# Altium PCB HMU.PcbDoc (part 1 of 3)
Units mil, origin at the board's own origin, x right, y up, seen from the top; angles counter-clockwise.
Board outline 6247.81 x 4035.43 mil, 4 copper layers (Top Layer, Mid-Layer 1, Mid-Layer 2, Bottom Layer), stack 90 mil thick; 310 components, 201 nets, 779 pads, 176 vias.
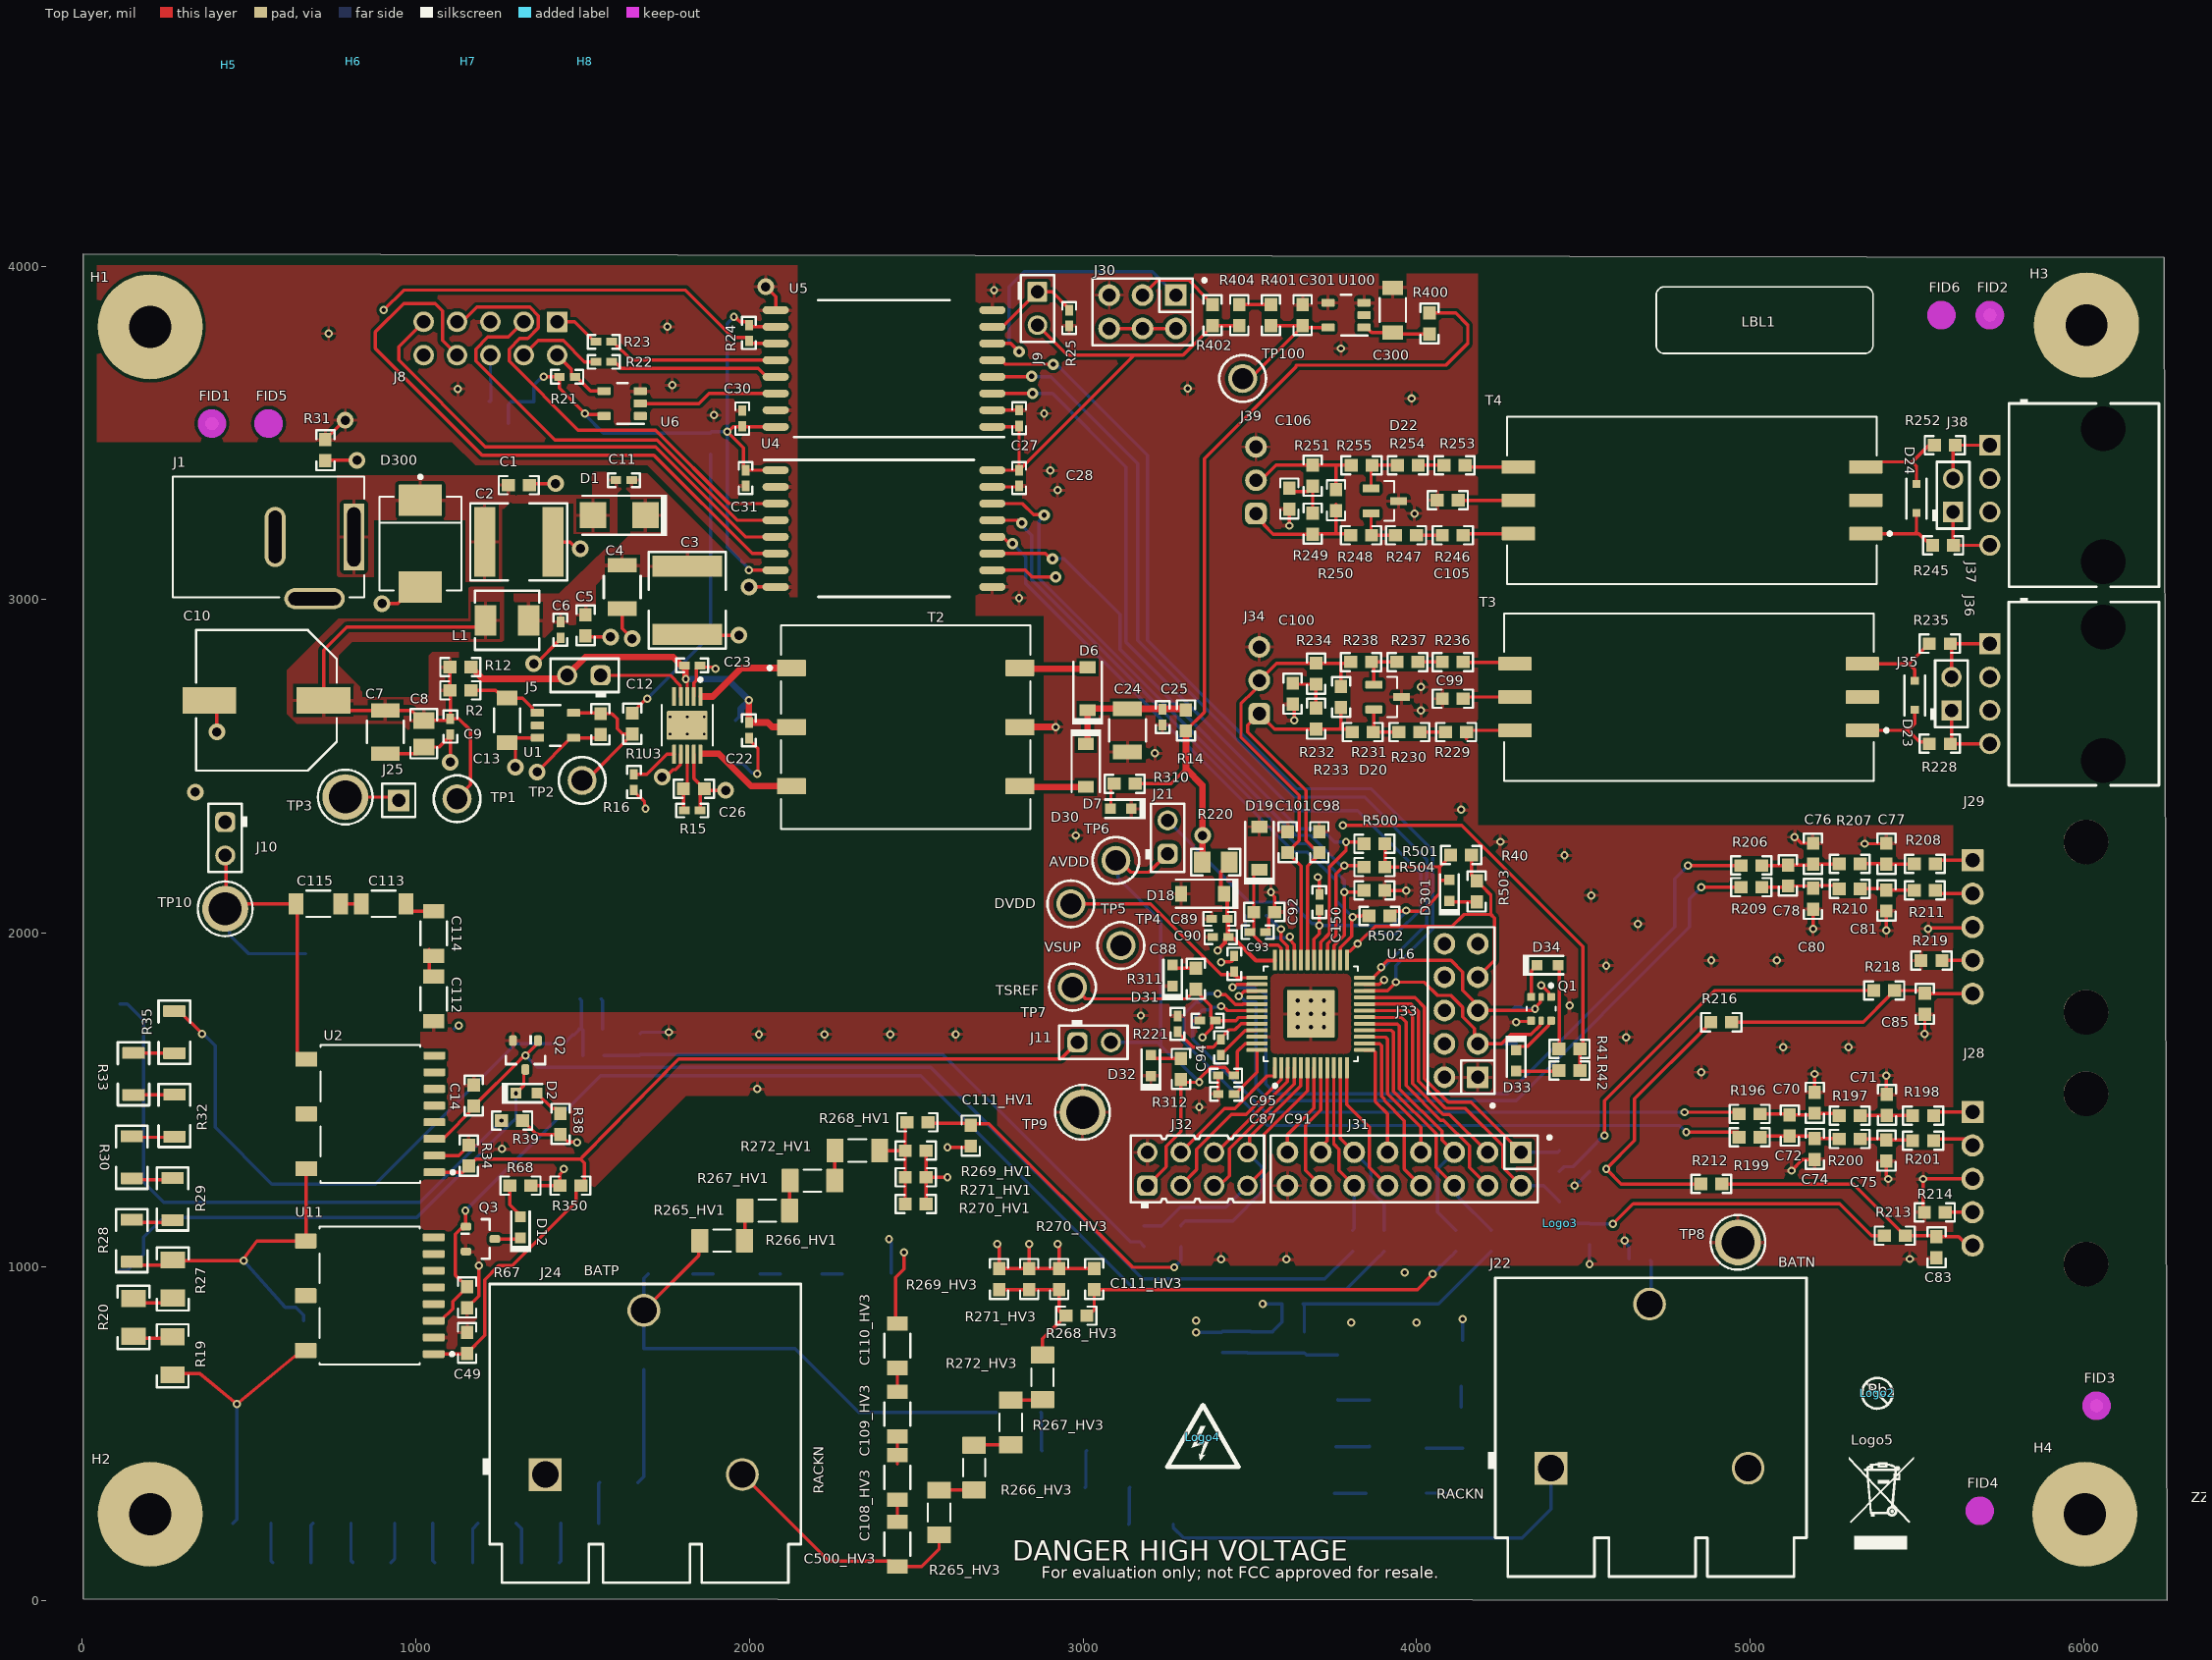
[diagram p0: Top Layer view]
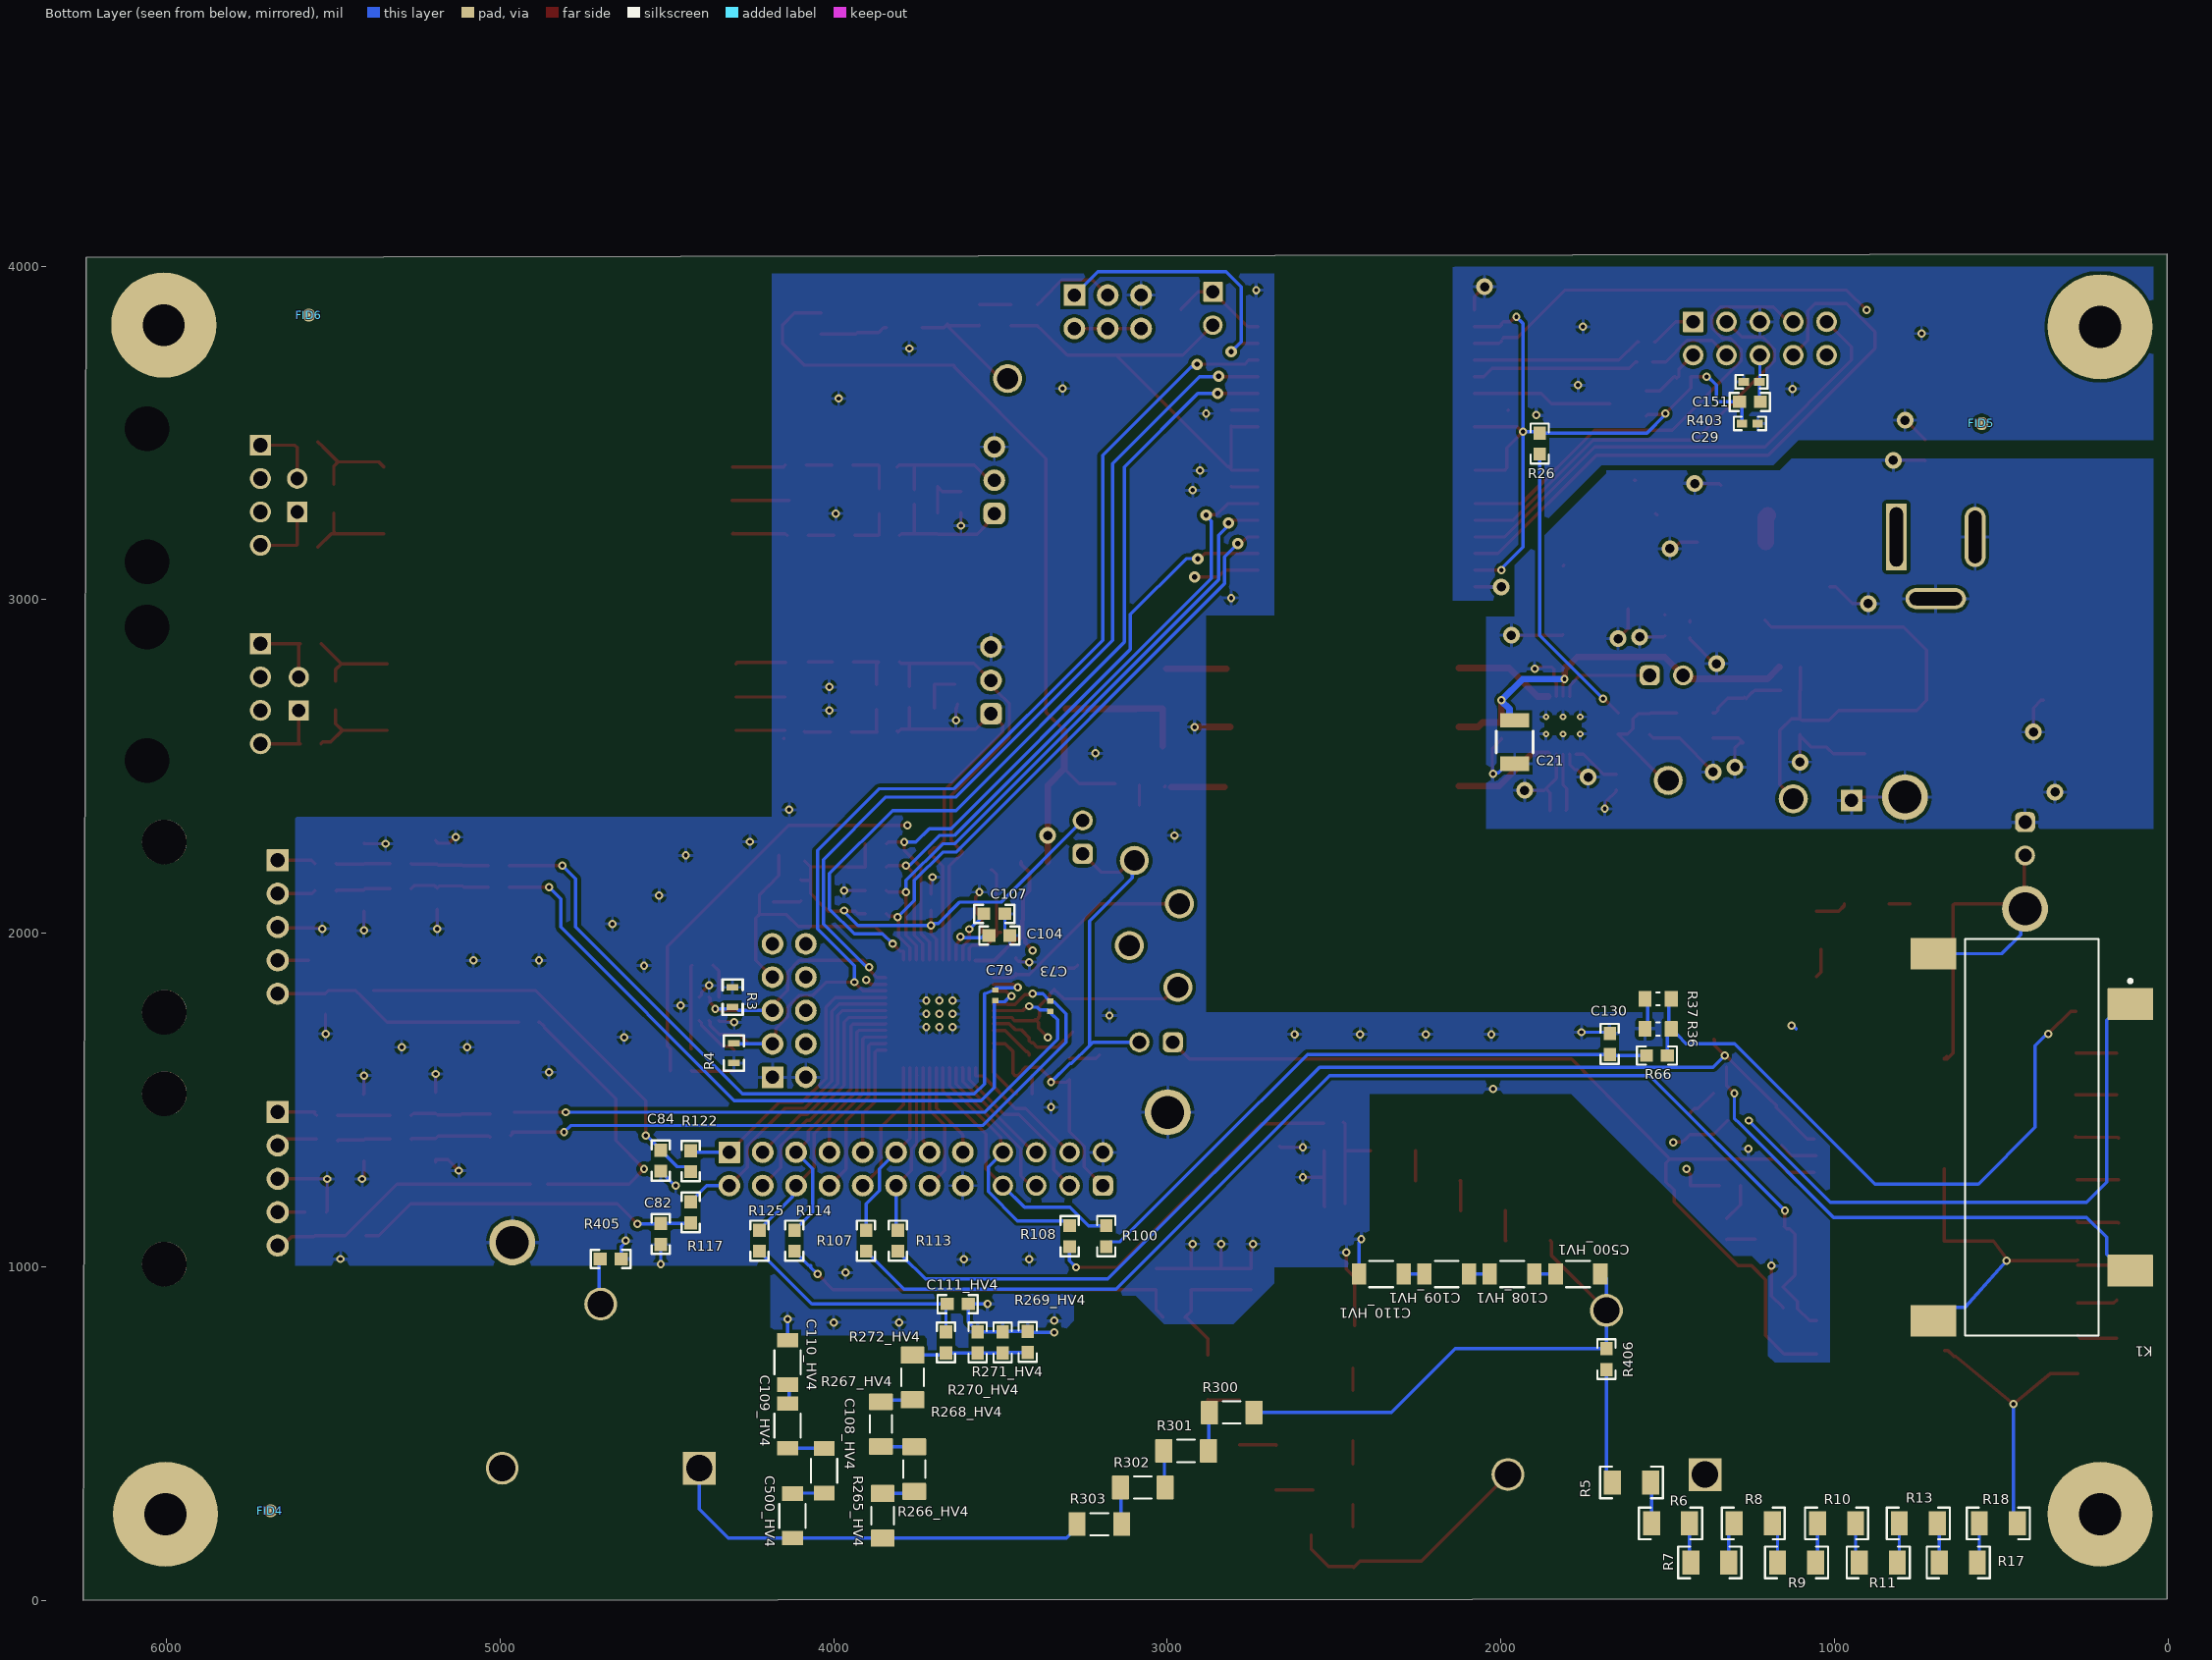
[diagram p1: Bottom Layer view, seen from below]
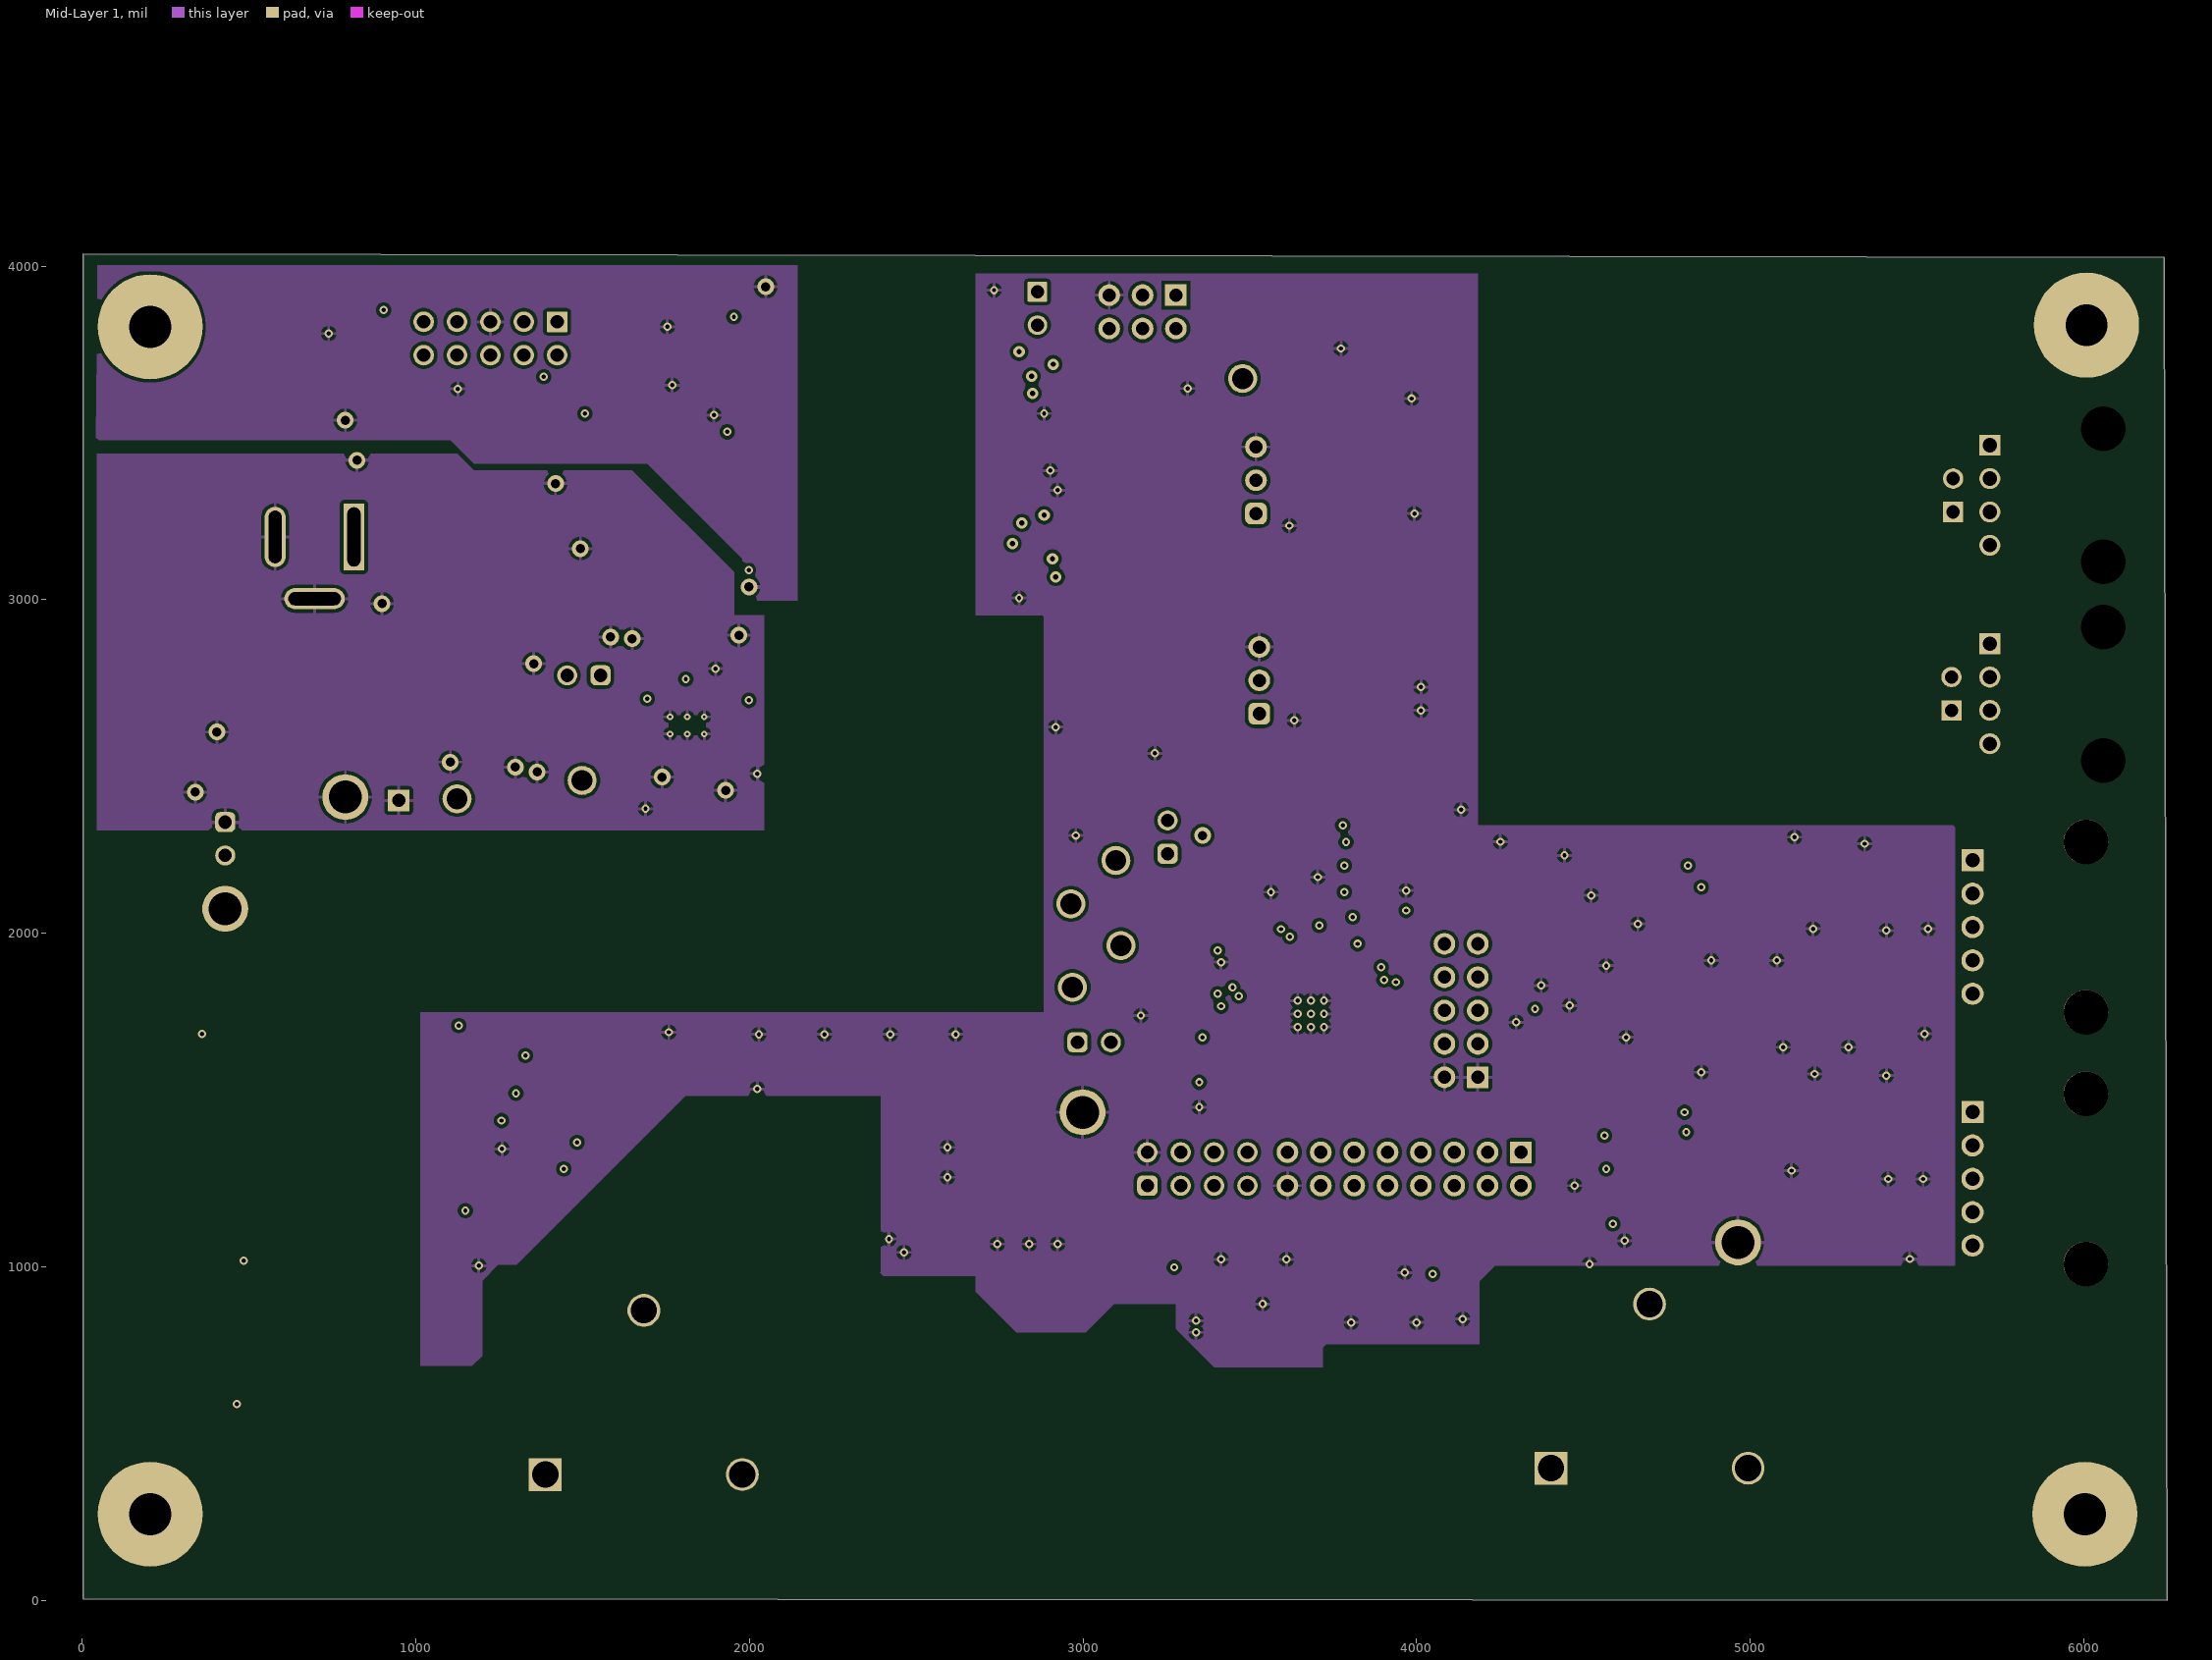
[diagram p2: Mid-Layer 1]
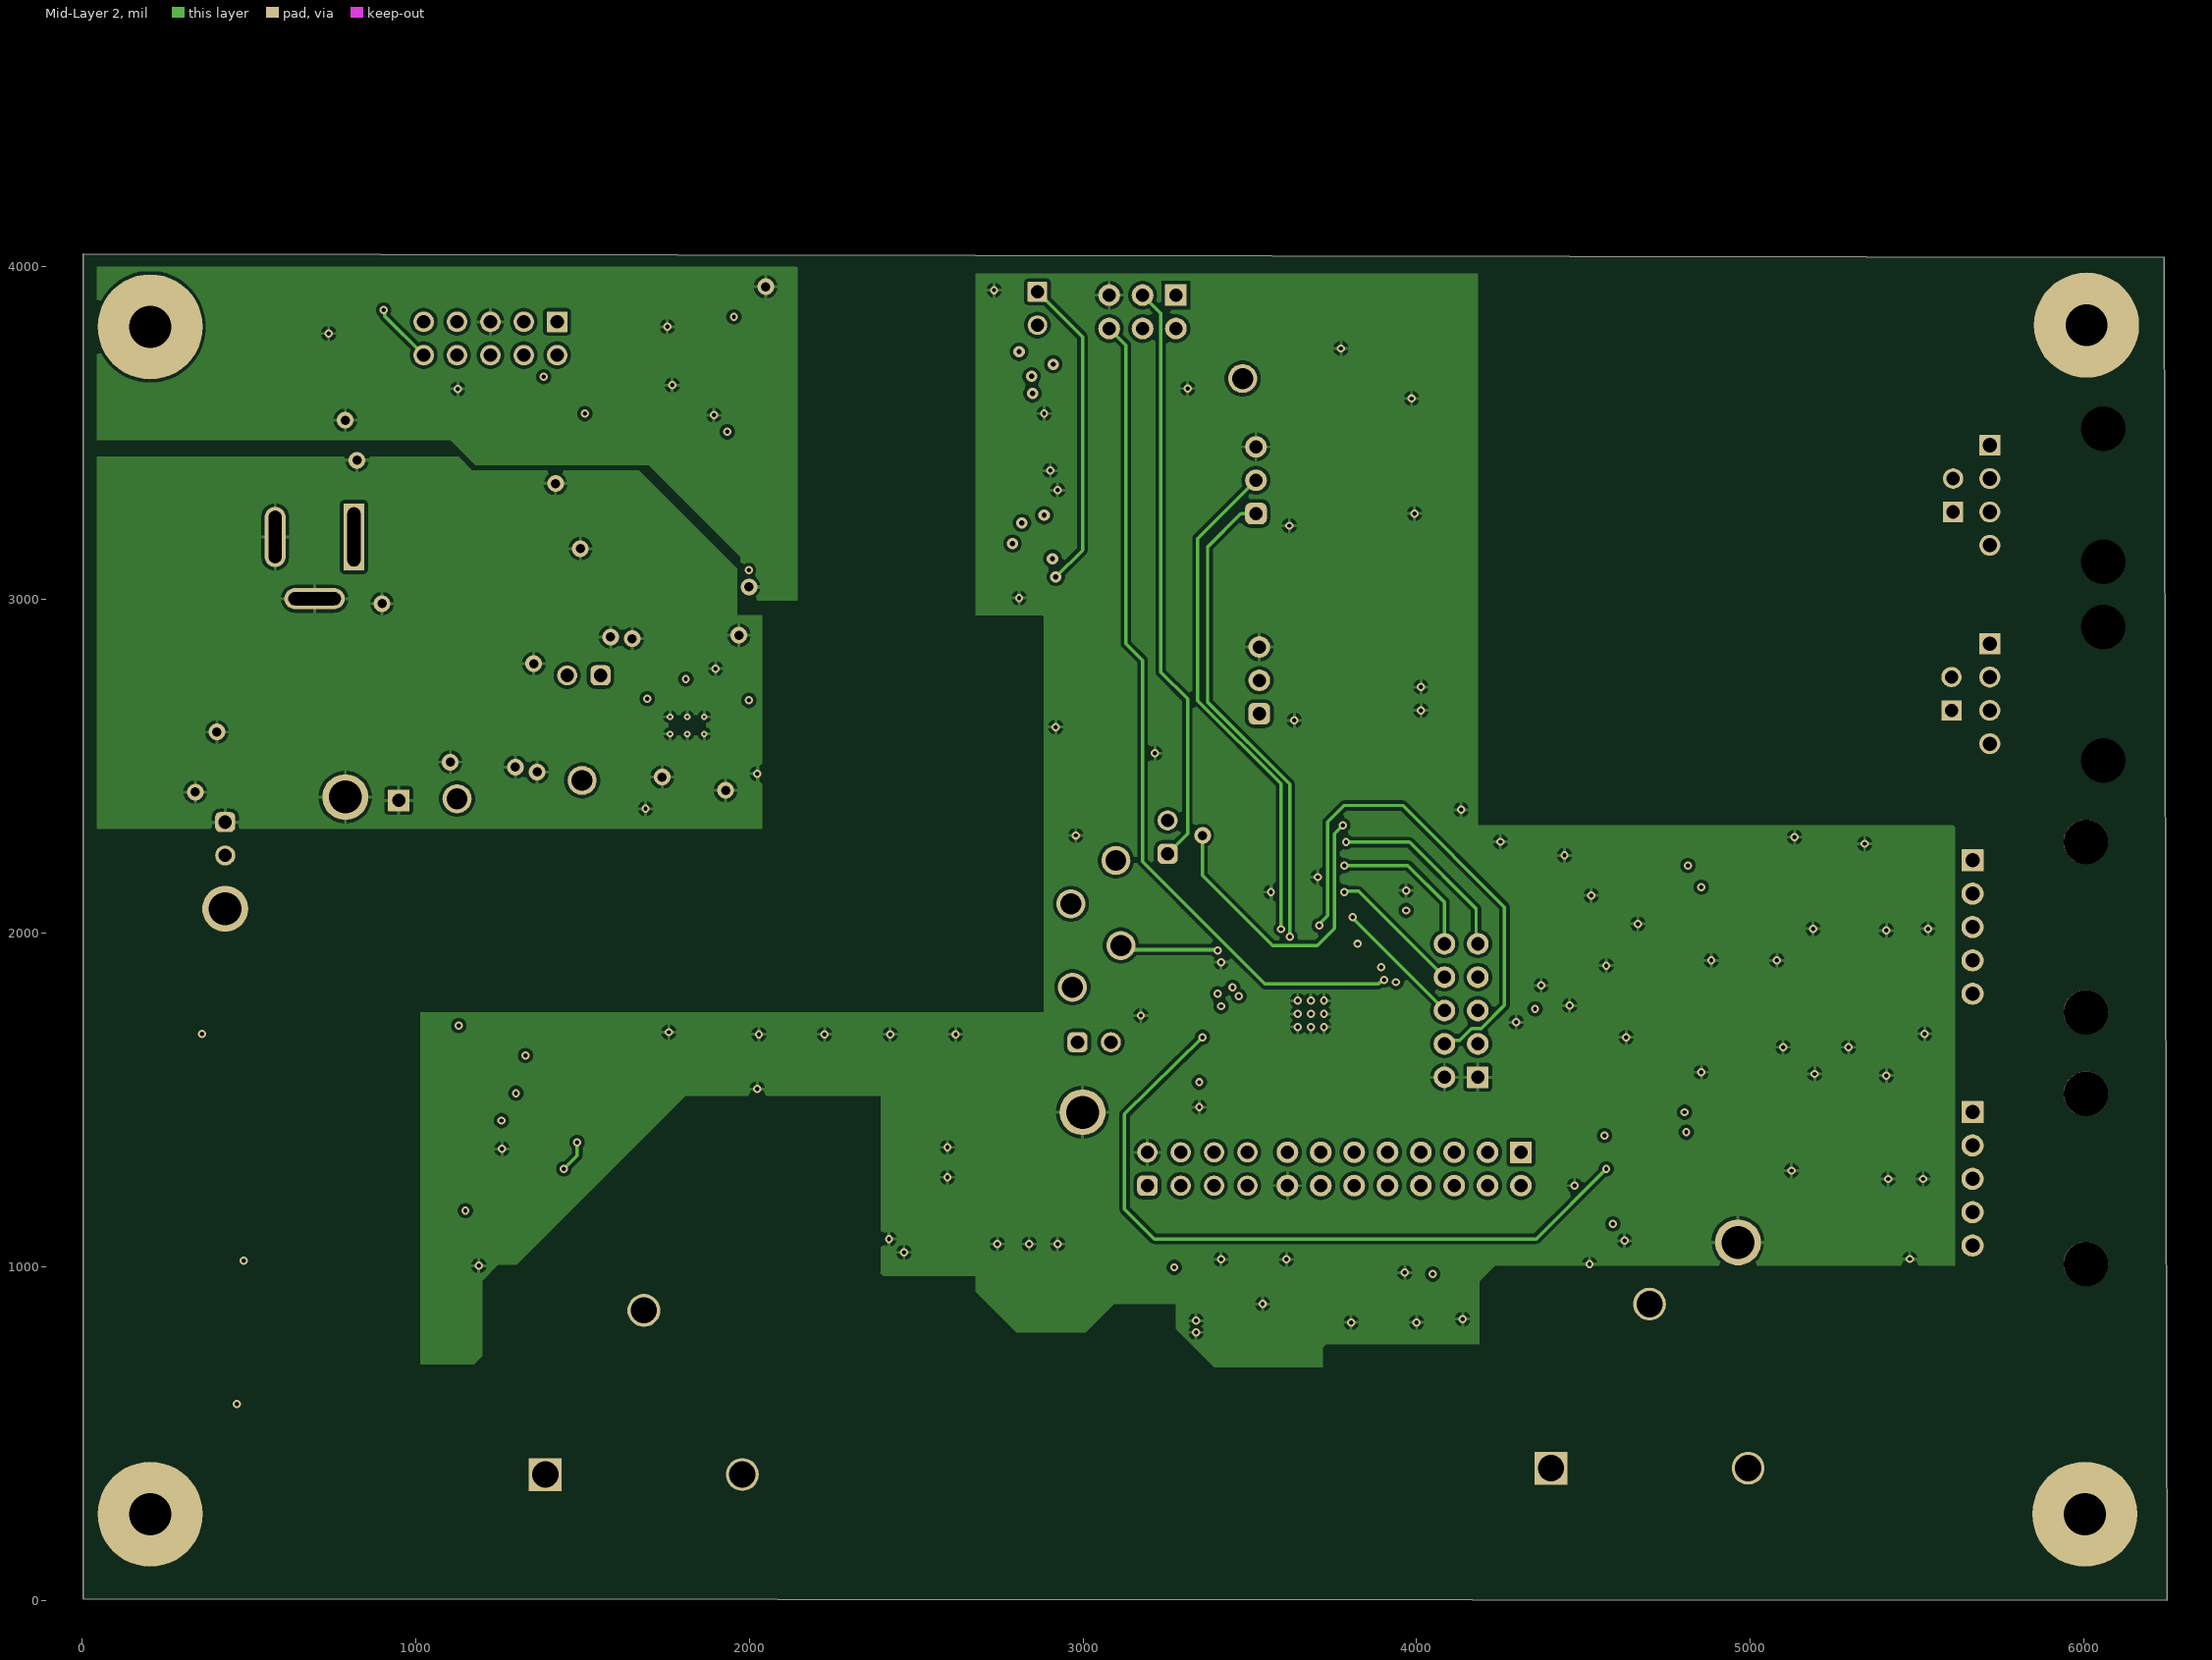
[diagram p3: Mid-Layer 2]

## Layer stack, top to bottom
Top Solder: solder mask 0.4, Solder Resist, Dk 3.5
Top Layer: signal copper 1.4
Dielectric1: core 59.2, FR-4 High Tg, Dk 4.8
Mid-Layer 1: signal copper 1.4
Dielectric2: dielectric 12.6, FR-4, Dk 4.8
Mid-Layer 2: signal copper 1.4
Dielectric3: dielectric 12.6, FR-4, Dk 4.8
Bottom Layer: signal copper 1.4
Bottom Solder: solder mask 0.4, Solder Resist, Dk 3.5

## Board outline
2.19,3.66 2.19,4035.43 6240.16,4025.59 6250,0

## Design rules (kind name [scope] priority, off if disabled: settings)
AcuteAngle [All] p1: minimum=4.50000000000000E+0001 checktracksonly=FALSE
AssemblyTestPointUsage [All] p1: valid=2
BoardOutlineClearance BoardOutlineClearance_MountingHoles [OnCopper and InComponentClass('Mounting Holes')] p1: gap=39.37 ignorepadtopadclearanceinfootprint=FALSE
BoardOutlineClearance BoardOutlineClearance_Poly [OnCopper and IsPoly] p2: gap=25 ignorepadtopadclearanceinfootprint=FALSE
BoardOutlineClearance [OnCopper and Not InComponentClass('Logo') and not InComponentClass('FiducialMark') and not InRegion(1000,500,4000,800) and not InPoly] p3: gap=40 ignorepadtopadclearanceinfootprint=FALSE
Clearance Clearance_Keepouts [((IsTrack Or IsArc) And Not InPoly) And IsFree and IsKeepOut vs ((IsTrack Or IsArc) And Not InPoly) And IsFree and IsKeepOut] p1: gap=0 ignorepadtopadclearanceinfootprint=TRUE
Clearance Clearance_Poly [InPolygon] p2: gap=10 ignorepadtopadclearanceinfootprint=TRUE
Clearance Clearance_FiducialMark [IsKeepOut and InComponentClass('FiducialMark') vs IsPad and InComponentClass('FiducialMark')] p3: gap=0 ignorepadtopadclearanceinfootprint=TRUE
Clearance [All] p4: gap=7.87 ignorepadtopadclearanceinfootprint=TRUE
ComponentClearance ComponentClearance_MountingHoles_FiducialMarks [InComponentClass('Mounting Holes') vs InComponentClass('FiducialMark')] p1: gap=50 collisioncheckmode=3 verticalgap=10 showdistances=FALSE
ComponentClearance ComponentClearance_Shunt [InComponentClass('Header') vs InComponentClass('Shunt')] p2: gap=0 collisioncheckmode=3 verticalgap=0 showdistances=FALSE
ComponentClearance ComponentClearance_Logo [InComponentClass('Logo')] p3: gap=30 collisioncheckmode=3 verticalgap=10 showdistances=FALSE
ComponentClearance ComponentClearance_ScrewToNut [(HasFootprint('NY PMS 440 0025 PH')) vs (HasFootprint('Keystone_1902C'))] p4: gap=5 collisioncheckmode=3 verticalgap=10 showdistances=FALSE
ComponentClearance ComponentClearance_MountingHoles [InComponentClass('Mounting Holes')] p5: gap=100 collisioncheckmode=3 verticalgap=100000 showdistances=FALSE
ComponentClearance ComponentClearance_SmallPassives [HasFootprint('0201*') or HasFootprint('0402*') or HasFootprint('0508') or HasFootprint('0603*') or HasFootprint('0612') or HasFootprint('0805*') or HasFootprint('0815*') or HasFootprint('0830*') or HasFootprint('1206*') or HasFootprint('1210*') or HasFootprint('1808*') or HasFootprint('1812*') or HasFootprint('1825*') or HasFootprint('2010*') or HasFootprint('2220*') or HasFootprint('2225*') or HasFootprint('2512*') or HasFootprint('2728*') or HasFootprint('3518*') vs HasFootprint('0201*') or HasFootprint('0402*') or HasFootprint('0508') or HasFootprint('0603*') or HasFootprint('0612') or HasFootprint('0805*') or HasFootprint('0815*') or HasFootprint('0830*') or HasFootprint('1206*') or HasFootprint('1210*') or HasFootprint('1808*') or HasFootprint('1812*') or HasFootprint('1825*') or HasFootprint('2010*') or HasFootprint('2220*') or HasFootprint('2225*') or HasFootprint('2512*') or HasFootprint('2728*') or HasFootprint('3518*')] p6: gap=14.96 collisioncheckmode=3 verticalgap=10 showdistances=FALSE
ComponentClearance ComponentClearance_THtoSMT [IsThruComponent vs IsSMTComponent] p7: gap=30 collisioncheckmode=3 verticalgap=30 showdistances=FALSE
ComponentClearance ComponentClearance_THtoTH [IsThruComponent vs IsThruComponent] p8: gap=20 collisioncheckmode=3 verticalgap=30 showdistances=FALSE
ComponentClearance [All] p9: gap=20 collisioncheckmode=3 verticalgap=10 showdistances=FALSE
DiffPairsRouting [All] p1: maxlimit=100 minlimit=10 mostfreqgap=10 toplayer_minwidth=15 toplayer_maxwidth=15 toplayer_prefwidth=15 midlayer1_minwidth=15 midlayer1_maxwidth=15 midlayer1_prefwidth=15 midlayer2_minwidth=15 midlayer2_maxwidth=15 midlayer2_prefwidth=15 bottomlayer_minwidth=15 bottomlayer_maxwidth=15 bottomlayer_prefwidth=15 maxuncoupledlength=1000
FabricationTestPointUsage TestPointUsage [All] p1: valid=2 allowmultiple=FALSE
FabricationTestpoint Testpoint [All] p1: side=3 testpointundercomponent=TRUE minsize=40 maxsize=100 preferedsize=60 minholesize=0 maxholesize=40 preferedholesize=32 testpointgrid=1 allowsidetop=TRUE allowsidebottom=TRUE usegrid=TRUE gridtolerance=0.01
FanoutControl Fanout_LCC [IsLCC] p1: bgadir=Out bgaviamode=Centered fanoutstyle=Auto fanoutdirection=Alternating viagrid=1 // Fanout_LCC (Default Rule)
FanoutControl Fanout_BGA [IsBGA] p2: bgadir=Out bgaviamode=Centered fanoutstyle=Auto fanoutdirection=Alternating viagrid=1 // Fanout_BGA (Default Rule)
FanoutControl Fanout_Default [All] p4: bgadir=Out bgaviamode=Centered fanoutstyle=Auto fanoutdirection=Alternating viagrid=1 // Fanout_Default (Default Rule)
FanoutControl Fanout_Small [(CompPinCount < 5)] p5: bgadir=Out bgaviamode=Centered fanoutstyle=Auto fanoutdirection=OutThenIn viagrid=1 // Fanout_Small (Default Rule)
HoleSize [All] p1: absolutevalues=TRUE maxlimit=251 minlimit=7.87 maxpercent=80.000 minpercent=20.000
MinimumAnnularRing MinimumAnnularRing_ThermalPadVias [IsVia and InAnyComponent] p1: minimumring=5.91
MinimumAnnularRing [All] p2: minimumring=5.9
MinimumSolderMaskSliver MinimumSolderMaskSliver_Logo [InComponentClass('Logo') vs InComponentClass('Logo')] p1: minsoldermaskwidth=0.7
MinimumSolderMaskSliver [All] p2: minsoldermaskwidth=3.94
PlaneConnect [All] p1: planeconnectstyle=Relief reliefexpansion=10 reliefentries=4 reliefconductorwidth=10 reliefairgap=10
PolygonConnect [All] p1: connectstyle=Relief reliefconductorwidth=10 reliefentries=4 polygonreliefangle="90 Angle" airgapwidth=10
RoutingVias ThermalPadVias [IsVia and InAnyComponent] p1: holewidth=7.87 width=19.68 viastyle="Through Hole" minholewidth=7.87 minwidth=12 maxholewidth=25 maxwidth=25
RoutingVias [All] p2: holewidth=16 width=34 viastyle="Through Hole" minholewidth=7.87 minwidth=24 maxholewidth=40 maxwidth=65
SilkToBoardRegionClearance [Not ((IsComment or IsDesignator) And (Hide <> 'False')) and not InRegion(1000,500,4000,800)] p1:
SilkToSilkClearance SilkToSilkClearance_Pb-FreeLogo [(HasFootprint('Pb-Free_Overlay_Medium') OR HasFootprint('Pb-Free_Overlay_Small')) vs (HasFootprint('Pb-Free_Overlay_Medium') OR HasFootprint('Pb-Free_Overlay_Small'))] p1: silktosilkclearance=0
SilkToSilkClearance [All] p2: silktosilkclearance=3.94
SilkToSolderMaskClearance SilkToComponentPadClearance [(IsPad or IsFill or IsRegion) and InAnycomponent] p1: minsilkscreentomaskgap=3 clearancetoexposedcopper=TRUE
SilkToSolderMaskClearance "Silk to Solder Mask Opening" [All] p2: minsilkscreentomaskgap=3.94 clearancetoexposedcopper=FALSE
SolderMaskExpansion [All] p1: expansion=1.97 istentingtop=FALSE
UnRoutedNet [All] p1: checkbadconnections=TRUE
Width [All] p1: maxlimit=100 minlimit=6 preferedwidth=10 checkconnectedcopper=TRUE
14 further rules are at their usual default settings.

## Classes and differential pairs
channel class HVSense_1CH: HV1 HV3 HV4
component class PWR: C1 C2 C3 C4 C5 C6 C7 C8 C9 C10 C11 C12 C13 C21 C22 C23 C24 C25 C26 C300 C301 D1 D6 D7 D300 J1 J5 L1 R1 R2 R12 R14 R15 R16 R400 R401 T2 TP1 TP2 TP3 TP100 U1 U3 U100
component class ISO: C27 C28 C29 C30 C31 C151 J8 J9 R3 R4 R21 R22 R23 R24 R25 R26 R31 R402 R403 R404 U4 U5 U6
component class IOM: R100 R107 R108 R113 R114 R117 R122 R125
component class IMD: C14 C49 C112 C113 C114 C115 C130 D2 D12 J10 J11 K1 Q2 Q3 R5 R6 R7 R8 R9 R10 R11 R13 R17 R18 R19 R20 R27 R28 R29 R30 R32 R33 R34 R35 R36 R37 R38 R39 R66 R67 R68 R350 TP10 U2 U11
component class HW: !PCB1 FID1 FID2 FID3 FID4 FID5 FID6 H1 H2 H3 H4 H5 H6 H7 H8 LBL1 Logo2 Logo3 Logo4 Logo5 ZZ2
component class HV4: C108_HV4 C109_HV4 C110_HV4 C111_HV4 C500_HV4 R265_HV4 R266_HV4 R267_HV4 R268_HV4 R269_HV4 R270_HV4 R271_HV4 R272_HV4
component class HV3: C108_HV3 C109_HV3 C110_HV3 C111_HV3 C500_HV3 R265_HV3 R266_HV3 R267_HV3 R268_HV3 R269_HV3 R270_HV3 R271_HV3 R272_HV3
component class HV1: C108_HV1 C109_HV1 C110_HV1 C111_HV1 C500_HV1 R265_HV1 R266_HV1 R267_HV1 R268_HV1 R269_HV1 R270_HV1 R271_HV1 R272_HV1
component class HMU: J21 J22 J24 J25 R300 R301 R302 R303 R405 R406
component class Header: J5 J9 J10 J11 J21 J25 J30 J31 J32 J33 J34 J39
component class CS: C70 C71 C72 C73 C74 C75 C76 C77 C78 C79 C80 C81 C82 C83 C84 C85 J28 J29 R196 R197 R198 R199 R200 R201 R206 R207 R208 R209 R210 R211 R212 R213 R214 R216 R218 R219
component class COM: C98 C99 C100 C101 C104 C105 C106 C107 D20 D22 D23 D24 J34 J35 J36 J37 J38 J39 R228 R229 R230 R231 R232 R233 R234 R235 R236 R237 R238 R245 R246 R247 R248 R249 R250 R251 R252 R253 R254 R255 T3 T4
component class BQ: C87 C88 C89 C90 C91 C92 C93 C94 C95 C150 D18 D19 D30 D31 D32 D33 D34 D301 J30 J31 J32 J33 Q1 R40 R41 R42 R220 R221 R310 R311 R312 R500 R501 R502 R503 R504 TP4 TP5 TP6 TP7 TP8 TP9 U16
component class "Mounting Holes": H1 H2 H3 H4
component class FiducialMark: FID1 FID2 FID3 FID4 FID5 FID6
component class AssemblyNote: ZZ2
component class Label: LBL1

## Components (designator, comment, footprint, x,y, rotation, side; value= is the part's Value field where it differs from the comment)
C1 "CGA3E2X7R2A472K080AA" 0603 1308.27,3342.8 r0 top value=4700pF
C2 "CGA9P3X7S2A156M250KB" 2220_280 1308.27,3172.8 r0 top value=15uF
C3 "CGA9P3X7S2A156M250KB" 2220_280 1813.27,2997.8 r270 top value=15uF
C4 "CGA6P3X7S1H106K250AB" 1210_280 1618.27,3037.8 r270 top value=10uF
C5 "CGA3E3X8R1H104M080AB" 0603 1508.27,2922.8 r270 top value=0.1uF
C6 "CGA2B2C0G1H102J050BA" 0402 1433.27,2909.17 r270 top value=1000pF
C7 "CGA6P3X7S1H106K250AB" 1210_280 908.27,2602.8 r270 top value=10uF
C8 "CGA4J3X7R1H225K125AB" 0805_HV 1023.27,2597.8 r270 top value=2.2uF
C9 "CGA2B2C0G1H102J050BA" 0402 1103.27,2619.17 r270 top value=1000pF
C10 "EEE-FK1H221GP" SM_RADIAL_G 552.01,2697.8 r180 top value=220uF
C11 "GRM1555C1H102JA01D" 0402 1623.27,3357.8 r180 top value=1000pF
C12 "GRT188R61C475KE13D" 0603 1553.27,2626.3 r270 top value=4.7uF
C13 "GRT31CR61H106KE01L" 1206_180 1273.27,2637.8 r270 top value=10uF
C14 "GCM188R71E104KA57D" 0603 1158.27,1332.8 r90 top value=0.1uF
C21 "CGA6P3X7S1H106K250AB" 1210_280 1958.27,2572.8 r270 bottom value=10uF
C22 "GCM155R71H104KE02D" 0402 1998.27,2607.8 r270 top value=0.1uF
C23 "GCM155R71H104KE02D" 0402 1828.27,2802.8 r0 top value=0.1uF
C24 "CGA6P3X7S1H106K250AB" 1210_280 3133.27,2607.8 r270 top value=10uF
C25 "GCM155R71H104KE02D" 0402 3238.27,2647.8 r270 top value=0.1uF
C26 "GRM188R71A225KE15J" 0603 1833.27,2432.8 r0 top value=2.2uF
C27 "GCM155R71H104KE02D" 0402 2808.27,3544.17 r90 top value=0.1uF
C28 "GCM155R71H104KE02D" 0402 2808.27,3364.17 r270 top value=0.1uF
C29 "GCM155R71H104KE02D" 0402 1253.27,3527.8 r180 bottom value=0.1uF
C30 "GCM155R71H104KE02D" 0402 1978.27,3542.8 r90 top value=0.1uF
C31 "GCM155R71H104KE02D" 0402 1988.27,3364.17 r270 top value=0.1uF
C49 "GCM188R71E104KA57D" 0603 1153.27,771.3 r90 top value=0.1uF
C70 "GCM188R71E104KA57D" 0603 5193.27,1491.3 r270 top value=0.1uF
C71 "GCM188R71E104KA57D" 0603 5409.63,1484.8 r270 top value=0.1uF
C72 "GCM188R71E105KA64D" 0603 5118.2,1422.8 r270 top value=1uF
C73 "GCM1555C1H221JA16D" FP-GCM1555C1H221JA16D_0402-MFG 3350.96,1780.69 r90 bottom
C74 "GCM188R71E104KA57D" 0603 5193.27,1352.8 r270 top value=0.1uF
C75 "GCM188R71E104KA57D" 0603 5408.27,1347.8 r270 top value=0.1uF
C76 "GCM188R71E104KA57D" 0603 5188.27,2237.8 r270 top value=0.1uF
C77 "GCM188R71E104KA57D" 0603 5408.27,2237.8 r270 top value=0.1uF
C78 "GCM188R71E105KA64D" 0603 5113.2,2172.8 r270 top value=1uF
C79 "GCM1555C1H221JA16D" FP-GCM1555C1H221JA16D_0402-MFG 3515.55,1813.46 r270 bottom
C80 "GCM188R71E104KA57D" 0603 5188.27,2102.8 r270 top value=0.1uF
C81 "GCM188R71E104KA57D" 0603 5408.27,2097.8 r270 top value=0.1uF
C82 "GCM188R71E104KA57D" 0603 4518.27,1097.8 r270 bottom value=0.1uF
C83 "CGA3E2X7R2A223K080AA" 0603 5558.27,1057.8 r270 top value=0.022uF
C84 "GCM188R71E104KA57D" 0603 4518.27,1317.8 r270 bottom value=0.1uF
C85 "CGA3E2X7R2A223K080AA" 0603 5523.27,1787.8 r270 top value=0.022uF
C87 "GRM155R61A474KE15D" 0402 3428.27,1572.8 r180 top value=0.47uF
C88 "GRM155R61A474KE15D" 0402 3453.27,1907.8 r90 top value=0.47uF
C89 "GCM155R71H104KE02D" 0402 3409.02,2042.8 r180 top value=0.1uF
C90 "GCM155R71H472KA37D" 0402 3412.64,1987.8 r180 top value=4700pF
C91 "GCM155R71H104KE02D" 0402 3429.02,1517.8 r180 top value=0.1uF
C92 "GRT188R61C475KE13D" 0603 3543.27,2062.8 r0 top value=4.7uF
C93 "GCM155R71H104KE02D" 0402 3523.27,2002.8 r0 top value=0.1uF
C94 "GRM155R61A474KE15D" 0402 3413.27,1657.8 r90 top value=0.47uF
C95 "GRM155R61A474KE15D" 0402 3373.27,1737.8 r180 top value=0.47uF
C98 "CL10B221JB8NNNC" 0603 3708.27,2272.8 r90 top value=220pF
C99 "GCM1885C1H101JA16J" 0603 4108.27,2702.8 r180 top value=100pF
C100 "CL10B103KB8NCNC" 0603 3628.27,2717.8 r90 top value=0.01uF
C101 "CL10B221JB8NNNC" 0603 3613.27,2272.8 r270 top value=220pF
C104 "CL10B221JB8NNNC" 0603 3503.27,1992.8 r180 bottom value=220pF
C105 "GCM1885C1H101JA16J" 0603 4093.27,3297.8 r180 top value=100pF
C106 "CL10B103KB8NCNC" 0603 3618.27,3302.8 r90 top value=0.01uF
C107 "CL10B221JB8NNNC" 0603 3518.27,2057.8 r0 bottom value=220pF
C108_HV1 "C1206C102KGRACAUTO" 1206_180 1966.12,977.8 r0 bottom value=1000pF (schematic designator C108)
C108_HV3 "C1206C102KGRACAUTO" 1206_180 2443.27,367.8 r90 top value=1000pF (schematic designator C108)
C108_HV4 "C1206C102KGRACAUTO" 1206_180 4028.27,387.8 r90 bottom value=1000pF (schematic designator C108)
C109_HV1 "C1206C102KGRACAUTO" 1206_180 2162.19,977.8 r0 bottom value=1000pF (schematic designator C109)
C109_HV3 "C1206C102KGRACAUTO" 1206_180 2443.27,557.8 r90 top value=1000pF (schematic designator C109)
C109_HV4 "C1206C102KGRACAUTO" 1206_180 4138.27,522.8 r90 bottom value=1000pF (schematic designator C109)
C110_HV1 "C1206C102KGRACAUTO" 1206_180 2358.27,977.8 r0 bottom value=1000pF (schematic designator C110)
C110_HV3 "C1206C102KGRACAUTO" 1206_180 2443.27,762.8 r90 top value=1000pF (schematic designator C110)
C110_HV4 "C1206C102KGRACAUTO" 1206_180 4138.27,712.8 r90 bottom value=1000pF (schematic designator C110)
C111_HV1 "GRM1885C1H682JA01D" 0603 2663.27,1392.8 r270 top value=6800pF (schematic designator C111)
C111_HV3 "GRM1885C1H682JA01D" 0603 3033.27,962.8 r90 top value=6800pF (schematic designator C111)
C111_HV4 "GRM1885C1H682JA01D" 0603 3628.27,887.8 r180 bottom value=6800pF (schematic designator C111)
C112 "1206J2K00220KCT" 1206_180 1053.27,1802.8 r270 top value=22pF
C113 "1206J2K00220KCT" 1206_180 903.27,2087.8 r0 top value=22pF
C114 "1206J2K00220KCT" 1206_180 1053.27,1998.87 r270 top value=22pF
C115 "1206J2K00220KCT" 1206_180 707.19,2087.8 r0 top value=22pF
C130 "GRM1885C1H682JA01D" 0603 1673.27,1667.8 r90 bottom value=6800pF
C150 "GCM155R71H104KE02D" 0402 3708.27,2092.8 r90 top value=0.1uF
C151 "GCM155R71A104KA55D" 0402 1248.27,3652.8 r180 bottom value=0.1uF
C300 "GRT31CR61H106KE01L" 1206_180 3928.27,3867.8 r90 top value=10uF
C301 "GRT188R61C475KE13D" 0603 3658.27,3852.8 r90 top value=4.7uF
C500_HV1 "C1206C102KGRACAUTO" 1206_180 1768.27,977.8 r0 bottom value=1000pF (schematic designator C500)
C500_HV3 "C1206C102KGRACAUTO" 1206_180 2443.27,167.8 r90 top value=1000pF (schematic designator C500)
C500_HV4 "C1206C102KGRACAUTO" 1206_180 4123.27,252.8 r90 bottom value=1000pF (schematic designator C500)
D1 "RB058L-60TE25" SMA 1609.53,3252.8 r180 top value=60V
D2 "150060VS75000" WL-SMCW_GREEN 1331.38,1520 r0 top value=Green
D6 "MBR0530T1G" SOD-123 3013.27,2732.8 r90 top value=30V
D7 "MBR0530T1G" SOD-123 3008.27,2502.8 r270 top value=30V
D12 "150060VS75000" WL-SMCW_GREEN 1313.27,1117.8 r90 top value=Green
D18 "MMSZ4702-HE3-08" SOD-123 3358.27,2117.8 r180 top value=15V
D19 "BZT52B12-E3-08" SOD-123 3528.27,2254.25 r90 top value=12V
D20 "ESDS552DBZR" DBZ0003A-MFG 3913.27,2707.8 r0 top
D22 "ESDS552DBZR" DBZ0003A-MFG 3904.61,3295.39 r0 top
D23 "CDSOD323-T08SC" SOD-323-Bi 5493.27,2712.8 r270 top value=8V
D24 "CDSOD323-T08SC" SOD-323-Bi 5498.27,3302.8 r90 top value=8V
D30 "150060VS75000" WL-SMCW_GREEN 3113.27,2372.8 r180 top value=Green
D31 "150060VS75000" WL-SMCW_GREEN 3268.27,1872.8 r90 top value=Green
D32 "150060VS75000" WL-SMCW_GREEN 3203.27,1602.8 r90 top value=Green
D33 "150060RS75000" WL-SMCW_RED 4298.27,1617.8 r270 top value=Red
D34 "150060RS75000" WL-SMCW_RED 4392.52,1904.03 r0 top value=Red
D300 "SMCJ36A" FP-SMCJ36A_DO-214AB-MFG 1013.27,3167.8 r270 top
D301 "150060RS75000" WL-SMCW_RED 4098.07,2127.8 r90 top value=Red
FID1 "Fiducial" Fiducial10-20#1 388.27,3527.8 r90 top
FID2 "Fiducial" Fiducial10-20#1 5718.27,3852.8 r90 top
FID3 "Fiducial" Fiducial10-20#1 6038.27,582.8 r90 top
FID4 "Fiducial" Fiducial10-20#2 5688.27,267.8 r90 top
FID5 "Fiducial" Fiducial10-20#2 558.27,3527.8 r90 top
FID6 "Fiducial" Fiducial10-20#2 5573.27,3852.8 r90 top
H1 "NY PMS 440 0025 PH" "NY PMS 440 0025 PH" 203.27,3817.8 r0 top
H2 "NY PMS 440 0025 PH" "NY PMS 440 0025 PH" 203.27,257.8 r0 top
H3 "NY PMS 440 0025 PH" "NY PMS 440 0025 PH" 6008.27,3822.8 r0 top
H4 "NY PMS 440 0025 PH" "NY PMS 440 0025 PH" 6003.27,257.8 r0 top
H5 "1902C" Keystone_1902C 438.27,4602.8 r0 top
H6 "1902C" Keystone_1902C 811.5,4612.8 r0 top
H7 "1902C" Keystone_1902C 1156.5,4612.8 r0 top
H8 "1902C" Keystone_1902C 1506.5,4612.8 r0 top
J1 "PJ-002BH" FP-PJ-002BH_PTH_POWER_CONN_14MM4_9MM0-MFG 558.27,3187.8 r180 top
J5 "TSW-102-08-G-S" Samtec_TSW-102-08-x-S 1503.27,2772.8 r180 top
J8 "TSW-105-08-L-D-RA" FP-TSW-105-08-L-D-RA_HDR10-MFG 1223.27,3942.64 r180 top
J9 "PEC02SAAN" CONN_PEC02SAAN 2863.27,3872.8 r270 top
J10 "TSW-102-08-G-S" Samtec_TSW-102-08-x-S 428.27,2282.8 r270 top
J11 "TSW-102-08-G-S" Samtec_TSW-102-08-x-S 3033.27,1672.8 r0 top
J21 "TSW-102-08-G-S" Samtec_TSW-102-08-x-S 3253.27,2287.8 r90 top
J22 "1792119" Phoenix_1792119 4698.27,641.73 r0 top
J24 "1792119" Phoenix_1792119 1683.27,622.8 r0 top
J25 "TSW-101-07-G-S" TSW-101-07-G-S 948.27,2397.8 r0 top
J28 "705550039" 705550039 5908.27,1262.8 r90 top
J29 "705550039" 705550039 5908.27,2017.8 r90 top
J30 "TSW-103-07-G-D" TSW-103-07-G-D 3178.27,3862.8 r180 top
J31 "TSW-108-07-G-D" TSW-108-07-G-D 3962.64,1292.8 r180 top
J32 "TSW-104-08-L-D" Samtec_TSW-104-08-x-D 3342.64,1292.8 r90 top
J33 "TSW-105-07-G-D" TSW-105-07-G-D 4133.27,1767.8 r90 top
J34 "TSW-103-07-G-S" TSW-103-07-G-S 3528.27,2757.8 r90 top
J35 "HTSW-102-09-G-S" Samtec_HTSW-102-09-x-S 5603.27,2717.8 r90 top
J36 "70551-0038" Molex_70551-0038 5718.11,2717.8 r0 top
J37 "70551-0038" Molex_70551-0038 5718.27,3312.8 r0 top
J38 "HTSW-102-09-G-S" Samtec_HTSW-102-09-x-S 5608.27,3312.8 r90 top
J39 "TSW-103-07-G-S" TSW-103-07-G-S 3518.27,3357.8 r90 top
K1 "KT05-1A88-BV88926" FP-KT05-1A88-BV88926_SMT_RELAY_10MM2_30MM2-MFG 407.99,1387.8 r270 bottom
L1 "IHLP1616BZER2R2M01" IHLP-1616BZ 1273.27,2937.8 r180 top value=2.2uH
LBL1 "THT-14-423-10" Label_650x200 5043.27,3837.8 r0 top
Logo2 "Pb-Free Symbol" Pb-Free_Overlay_Small 5380.93,620.08 r0 top
Logo3 "FCC disclaimer" FCC_disclaimer 4430.28,1129.29 r90 top
Logo4 "DANGER HIGH VOLTAGE" IEC_HighVoltage_Small 3359.24,487.36 r0 top
Logo5 "WEEE logo" WEEE_Minimum 5391.09,324.8 r0 top
Q1 "2N7002BKS,115" FP-2N7002BKS,115_SOT363-MFG 4373.27,1772.8 r270 top
Q2 "2N7002BKVL" SOT-23L 1328.27,1634.51 r270 top value=60V
Q3 "2N7002BKVL" SOT-23L 1193.27,1082.8 r0 top value=60V
R1 "CRCW06030000Z0EA" 0603 1648.27,2627.8 r90 top value=0
R2 "CRCW06030000Z0EA" 0603 1133.27,2727.8 r0 top value=0
R3 "RR0816P-104-D" 0603_HR 4303.27,1807.8 r270 bottom value=100k
R4 "RR0816P-104-D" 0603_HR 4298.58,1640.08 r90 bottom value=100k
R5 "CRCW1206150KJNEA" 1206 1608.27,352.8 r0 bottom value=150k
R6 "CRCW1206150KJNEA" 1206 1491.18,230.04 r0 bottom value=150k
R7 "CRCW1206150KJNEA" 1206 1373.27,112.8 r0 bottom value=150k
R8 "CRCW1206150KJNEA" 1206 1243.27,230.04 r0 bottom value=150k
R9 "CRCW1206150KJNEA" 1206 1113.27,112.8 r0 bottom value=150k
R10 "CRCW1206150KJNEA" 1206 993.27,230.04 r0 bottom value=150k
R11 "CRCW1206150KJNEA" 1206 868.27,112.8 r0 bottom value=150k
R12 "CRCW06030000Z0EA" 0603 1133.27,2797.8 r0 top value=0
R13 "CRCW1206150KJNEA" 1206 748.27,230.04 r0 bottom value=150k
R14 "CRCW06030000Z0EA" 0603 3308.27,2637.8 r270 top value=0
R15 "CRCW040220K0JNED" 0402 1828.27,2367.8 r180 top value=20k
R16 "CRCW040220K0JNED" 0402 1653.27,2452.8 r90 top value=20k
R17 "CRCW1206150KJNEA" 1206 628.27,112.8 r0 bottom value=150k
R18 "CRCW1206150KJNEA" 1206 508.27,230.04 r0 bottom value=150k
R19 "ERJ-8ENF1004V" 1206 270.51,732.8 r90 top value=1.00Meg
R20 "ERJ-8ENF1004V" 1206 153.27,847.8 r90 top value=1.00Meg
R21 "CRCW0402100KDHEDP" 0402 1453.27,3667.8 r180 top value=100k
R22 "CRCW0402100RJNED" 0402 1563.27,3712.8 r0 top value=100
R23 "CRCW0402100RJNED" 0402 1563.27,3772.8 r0 top value=100
R24 "CRCW040210K0JNED" 0402 1998.27,3799.17 r90 top value=10k
R25 "CRCW040210K0JNED" 0402 2958.27,3844.17 r90 top value=10k
R26 "CRCW06030000Z0EA" 0603 1883.27,3467.8 r90 bottom value=0
R27 "ERJ-8ENF1004V" 1206 270.93,962.8 r90 top value=1.00Meg
R28 "TNPV1206750KBEEN" TNPV1206 148.27,1077.8 r270 top value=750k
R29 "TNPV1206750KBEEN" TNPV1206 270.64,1202.8 r270 top value=750k
R30 "TNPV1206750KBEEN" TNPV1206 148.27,1327.8 r270 top value=750k
R31 "CRCW06030000Z0EA" 0603 728.27,3447.8 r90 top value=0
R32 "TNPV1206750KBEEN" TNPV1206 275.9,1452.8 r270 top value=750k
R33 "TNPV1206750KBEEN" TNPV1206 153.27,1577.8 r270 top value=750k
R34 "CRCW06031M00JNEA" 0603 1173.27,1512.8 r270 top value=1.0Meg
R35 "TNPV1206750KBEEN" TNPV1206 275.64,1702.8 r270 top value=750k
R36 "PTFR0603B24K9NT" FP-PTFR0603B24K9NT_0603-MFG 1528.27,1712.8 r180 bottom value=24.9k
R37 "PTFR0603B24K9NT" FP-PTFR0603B24K9NT_0603-MFG 1528.27,1802.8 r180 bottom value=24.9k
R38 "CRCW06032K20JNEA" 0603 1433.27,1427.8 r270 top value=2.2k
R39 "CRCW06030000Z0EA" 0603 1288.27,1437.8 r180 top value=0
R40 "CRCW0603100KJNEA" 0603 4133.27,2234.03 r0 top value=100k
R41 "RT0603DRE07200RL" 0603 4458.27,1652.8 r0 top value=200
R42 "RT0603DRE07200RL" 0603 4458.27,1587.8 r0 top value=200
R66 "CRCW06030000Z0EA" 0603 1531.77,1632.8 r180 bottom value=0
R67 "CRCW06031M00JNEA" 0603 1153.27,907.8 r90 top value=1.0Meg
R68 "CRCW06032K20JNEA" 0603 1313.27,1242.8 r0 top value=2.2k
R100 "CRCW06030000Z0EA" 0603 3182.64,1091.3 r270 bottom value=0
R107 "CRCW06030000Z0EA" 0603 3902.64,1077.8 r270 bottom value=0
R108 "CRCW06030000Z0EA" 0603 3292.64,1091.3 r270 bottom value=0
R113 "CRCW06030000Z0EA" 0603 3807.64,1077.8 r270 bottom value=0
R114 "CRCW06030000Z0EA" 0603 4117.64,1077.8 r270 bottom value=0
R117 "CRCW06030000Z0EA" 0603 4428.27,1162.8 r270 bottom value=0
R122 "CRCW06030000Z0EA" 0603 4428.27,1316.3 r270 bottom value=0
R125 "CRCW06030000Z0EA" 0603 4222.64,1077.8 r270 bottom value=0
R196 "CRCW06030000Z0EA" 0603 4998.27,1457.8 r180 top value=0
R197 "CRCW06030000Z0EA" 0603 5298.27,1452.8 r180 top value=0
R198 "CRCW060310R0JNEA" 0603 5518.27,1452.8 r0 top value=10
R199 "CRCW06030000Z0EA" 0603 4998.27,1387.8 r180 top value=0
R200 "CRCW06030000Z0EA" 0603 5298.27,1382.8 r180 top value=0
R201 "CRCW060310R0JNEA" 0603 5518.27,1377.8 r0 top value=10
R206 "CRCW06030000Z0EA" 0603 5003.27,2202.8 r180 top value=0
R207 "CRCW06030000Z0EA" 0603 5298.27,2207.8 r180 top value=0
R208 "CRCW060310R0JNEA" 0603 5523.27,2207.8 r0 top value=10
R209 "CRCW06030000Z0EA" 0603 5003.27,2137.8 r180 top value=0
R210 "CRCW06030000Z0EA" 0603 5298.27,2132.8 r180 top value=0
R211 "CRCW060310R0JNEA" 0603 5523.27,2127.8 r0 top value=10
R212 "CRCW060310K0FKEA" 0603 4883.27,1247.8 r180 top value=10.0k
R213 "CRCW06031K00JNEA" 0603 5433.27,1092.8 r0 top value=1.0k
R214 "CRCW060310R0JNEA" 0603 5553.27,1162.8 r0 top value=10
R216 "CRCW060310K0FKEA" 0603 4913.27,1732.8 r180 top value=10.0k
R218 "CRCW06031K00JNEA" 0603 5401.77,1827.8 r0 top value=1.0k
R219 "CRCW060310R0JNEA" 0603 5543.27,1917.8 r0 top value=10
R220 "CRCW080551R0JNEA" 0805_HV 3397.64,2212.8 r0 top value=51
R221 "CRCW04020000Z0ED" 0402 3283.27,1727.8 r90 top value=0
R228 "RC0603JR-070RL" 0603 5568.27,2567.8 r180 top value=0
R229 "RC0603JR-070RL" 0603 4118.27,2602.8 r180 top value=0
R230 "CRCW060310R0JNEA" 0603 3978.27,2602.8 r180 top value=10
R231 "CRCW060343R0JNEA" 0603 3838.27,2602.8 r180 top value=43
R232 "RC0603FR-07499RL" 0603 3698.27,2642.8 r270 top value=499
R233 "CRCW06031K00FKEA" 0603 3773.27,2707.8 r270 top value=1.00k
R234 "RC0603FR-07499RL" 0603 3698.27,2777.8 r270 top value=499
R235 "RC0603JR-070RL" 0603 5568.27,2867.8 r180 top value=0
R236 "RC0603JR-070RL" 0603 4108.27,2812.8 r180 top value=0
R237 "CRCW060310R0JNEA" 0603 3972.36,2812.8 r180 top value=10
R238 "CRCW060343R0JNEA" 0603 3833.27,2812.8 r180 top value=43
R245 "RC0603JR-070RL" 0603 5578.27,3162.8 r180 top value=0
R246 "RC0603JR-070RL" 0603 4108.27,3192.8 r180 top value=0
R247 "CRCW060310R0JNEA" 0603 3968.27,3192.8 r180 top value=10
R248 "CRCW060343R0JNEA" 0603 3833.27,3192.8 r180 top value=43
R249 "RC0603FR-07499RL" 0603 3688.27,3227.8 r270 top value=499
R250 "CRCW06031K00FKEA" 0603 3758.27,3297.8 r270 top value=1.00k
R251 "RC0603FR-07499RL" 0603 3688.27,3371.3 r270 top value=499
R252 "RC0603JR-070RL" 0603 5583.27,3462.8 r180 top value=0
R253 "RC0603JR-070RL" 0603 4113.27,3402.8 r180 top value=0
R254 "CRCW060310R0JNEA" 0603 3973.27,3402.8 r180 top value=10
R255 "CRCW060343R0JNEA" 0603 3834.76,3402.8 r180 top value=43
R265_HV1 "CHV1206-FX-1504ELF" FP-CHV1206-FX-1504ELF_1206-MFG 1918.27,1077.8 r180 top value=1.5M (schematic designator R265)
R265_HV3 "CHV1206-FX-1504ELF" FP-CHV1206-FX-1504ELF_1206-MFG 2568.27,262.8 r270 top value=1.5M (schematic designator R265)
R265_HV4 "CHV1206-FX-1504ELF" FP-CHV1206-FX-1504ELF_1206-MFG 3853.27,252.8 r270 bottom value=1.5M (schematic designator R265)
R266_HV1 "CHV1206-FX-1504ELF" FP-CHV1206-FX-1504ELF_1206-MFG 2053.27,1167.8 r180 top value=1.5M (schematic designator R266)
R266_HV3 "CHV1206-FX-1504ELF" FP-CHV1206-FX-1504ELF_1206-MFG 2673.27,397.8 r270 top value=1.5M (schematic designator R266)
R266_HV4 "CHV1206-FX-1504ELF" FP-CHV1206-FX-1504ELF_1206-MFG 3758.27,392.8 r270 bottom value=1.5M (schematic designator R266)
R267_HV1 "CHV1206-FX-1504ELF" FP-CHV1206-FX-1504ELF_1206-MFG 2188.27,1257.8 r180 top value=1.5M (schematic designator R267)
R267_HV3 "CHV1206-FX-1504ELF" FP-CHV1206-FX-1504ELF_1206-MFG 2783.27,532.8 r270 top value=1.5M (schematic designator R267)
R267_HV4 "CHV1206-FX-1504ELF" FP-CHV1206-FX-1504ELF_1206-MFG 3858.27,527.8 r270 bottom value=1.5M (schematic designator R267)
R268_HV1 "CRCW06030000Z0EA" 0603 2503.27,1432.8 r180 top value=0 (schematic designator R268)
R268_HV3 "CRCW06030000Z0EA" 0603 2979.76,852.8 r180 top value=0 (schematic designator R268)
R268_HV4 "CRCW06030000Z0EA" 0603 3663.27,772.8 r270 bottom value=0 (schematic designator R268)
R269_HV1 "RC0603FR-0749K9L" 0603 2498.27,1347.8 r180 top value=49.9k (schematic designator R269)
R269_HV3 "RC0603FR-0749K9L" 0603 2748.27,962.8 r270 top value=49.9k (schematic designator R269)
R269_HV4 "RC0603FR-0749K9L" 0603 3418.27,774.29 r270 bottom value=49.9k (schematic designator R269)
R270_HV1 "RC0603FR-0749K9L" 0603 2498.27,1187.8 r180 top value=49.9k (schematic designator R270)
R270_HV3 "RC0603FR-0749K9L" 0603 2928.27,962.8 r270 top value=49.9k (schematic designator R270)
R270_HV4 "RC0603FR-0749K9L" 0603 3568.27,772.8 r270 bottom value=49.9k (schematic designator R270)
R271_HV1 "RC0603FR-0749K9L" 0603 2498.27,1267.8 r180 top value=49.9k (schematic designator R271)
R271_HV3 "RC0603FR-0749K9L" 0603 2838.27,962.8 r270 top value=49.9k (schematic designator R271)
R271_HV4 "RC0603FR-0749K9L" 0603 3493.27,772.8 r270 bottom value=49.9k (schematic designator R271)
R272_HV1 "CHV1206-FX-1504ELF" FP-CHV1206-FX-1504ELF_1206-MFG 2323.27,1347.8 r180 top value=1.5M (schematic designator R272)
R272_HV3 "CHV1206-FX-1504ELF" FP-CHV1206-FX-1504ELF_1206-MFG 2878.27,667.8 r270 top value=1.5M (schematic designator R272)
R272_HV4 "CHV1206-FX-1504ELF" FP-CHV1206-FX-1504ELF_1206-MFG 3763.27,667.8 r270 bottom value=1.5M (schematic designator R272)
R300 "CHV1206-FX-1504ELF" FP-CHV1206-FX-1504ELF_1206-MFG 2806.34,562.8 r180 bottom value=1.5M
R301 "CHV1206-FX-1504ELF" FP-CHV1206-FX-1504ELF_1206-MFG 2943.27,447.8 r180 bottom value=1.5M
R302 "CHV1206-FX-1504ELF" FP-CHV1206-FX-1504ELF_1206-MFG 3073.27,337.8 r180 bottom value=1.5M
R303 "CHV1206-FX-1504ELF" FP-CHV1206-FX-1504ELF_1206-MFG 3203.27,227.8 r180 bottom value=1.5M
R310 "CRCW06032K20JNEA" 0603 3124.76,2447.8 r0 top value=2.2k
R311 "CRCW06032K20JNEA" 0603 3338.27,1862.8 r270 top value=2.2k
R312 "CRCW06032K20JNEA" 0603 3293.27,1592.8 r270 top value=2.2k
R350 "CRCW06030000Z0EA" 0603 1463.27,1242.8 r180 top value=0
R400 "CRCW06030000Z0EA" 0603 4038.27,3827.8 r270 top value=0
R401 "CRCW06030000Z0EA" 0603 3563.27,3852.8 r90 top value=0
R402 "CRCW06030000Z0EA" 0603 3388.27,3852.8 r270 top value=0
R403 "CRCW06030000Z0EA" 0603 1253.27,3592.8 r0 bottom value=0
R404 "CRCW06030000Z0EA" 0603 3468.27,3852.8 r270 top value=0
R405 "CRCW06030000Z0EA" 0603 4668.27,1022.8 r180 bottom value=0
R406 "CRCW06030000Z0EA" 0603 1683.27,722.8 r90 bottom value=0
R500 "CRCW0603100KJNEA" 0603 3873.27,2267.8 r0 top value=100k
R501 "CRCW0603100KJNEA" 0603 3873.27,2197.8 r0 top value=100k
R502 "CRCW0603100KJNEA" 0603 3888.27,2051.36 r0 top value=100k
R503 "CRCW0603100KJNEA" 0603 4180.28,2124.88 r270 top value=100k
R504 "CRCW0603100KJNEA" 0603 3873.27,2127.8 r0 top value=100k
T2 "HCTSM151207FAL" FP-HCTSM151207FAL_SMT_XFRMR_21MM3_15MM0-MFG 2468.27,2617.8 r0 top
T3 "LKBMT10B" FP-LKBMT10B_SMT_XFRMR_27MM9_12MM5-MFG 4815.63,2707.8 r180 top
T4 "LKBMT10B" FP-LKBMT10B_SMT_XFRMR_27MM9_12MM5-MFG 4825.63,3297.8 r180 top
TP1 "24V_LV" Keystone5012 1123.27,2402.8 r0 top
TP2 "5V_LV" Keystone5012 1498.27,2457.8 r0 top
TP3 "GND_LV" Keystone1598-2 788.27,2407.8 r0 top
TP4 "VSUP" Keystone5012 3113.27,1962.8 r0 top
TP5 "DVDD" Keystone5012 2963.27,2087.8 r0 top
TP6 "AVDD" Keystone5012 3098.27,2217.8 r0 top
TP7 "TSREF" Keystone5012 2968.27,1837.8 r0 top
TP8 "GND" Keystone1598-2 4963.27,1072.8 r0 top
TP9 "GND" Keystone1598-2 2998.27,1462.8 r0 top
TP10 "PE" Keystone1598-2 428.27,2072.8 r0 top
TP100 "5V_HV" Keystone5012 3478.27,3662.8 r90 top
U1 "TPS7B6950QDBVRQ1" DBV0005A_N 1418.27,2622.8 r0 top
U2 "TPSI2140QDWQRQ1" DWQ0011A-MFG 863.27,1457.8 r180 top
U3 "SN6507DGQR" DGQ0010D-C01-MFG 1813.27,2622.8 r270 top
U4 "ISO7841DWWR" DWW0016A_N 2403.07,3212.8 r0 top
U5 "ISO7841DWWR" DWW0016A_N 2403.27,3692.8 r180 top
U6 "SN74LVC1G07QDBVRQ1" DBV0005A_N 1618.27,3587.8 r180 top
U11 "TPSI2140QDWQRQ1" DWQ0011A-MFG 861.34,912.8 r180 top
U16 "BQ79731-Q1" PHP0048E-MFG 3682.64,1757.8 r90 top
U100 "TPS7B6950QDBVRQ1" DBV0005A_N 3788.27,3852.8 r180 top
ZZ2 "These assemblies are ESD sensitive, ESD precautions shall be observed." AssemblyNote 6335.54,247.49 r90 top

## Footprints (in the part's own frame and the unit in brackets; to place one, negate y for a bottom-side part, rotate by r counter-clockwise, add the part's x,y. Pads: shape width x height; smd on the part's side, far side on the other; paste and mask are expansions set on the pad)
0402 [mm] "0402 from SM-752 data"
  rect 0.8x0.6 smd: 1(-0.6,0) 2(0.6,0)
  silkscreen extent -1.22,-0.52 1.22,0.52, body extent -0.55,-0.3 0.55,0.3, height 0.6
0603 [mm] "0603 from SM-752 data"
  rect 1x0.95 smd: 1(-0.8,0) 2(0.8,0)
  silkscreen extent -1.52,-0.69 1.52,0.69, body extent -0.87,-0.47 0.87,0.47, height 1
0603_HR [mm] "0603"
  rect 0.5x0.9 smd: 1(-0.75,0) 2(0.75,0)
  silkscreen extent -1.35,-0.75 1.35,0.77, body extent -0.82,-0.47 0.82,0.47, height 0.5
0805_HV [mil] "0805 with 30mil clearance between pads"
  rect 50x63 smd: 1(-40,0) 2(40,0)
  silkscreen extent -74,-40 74,40, body extent -43,-29 43,29, height 57
1206 [mm] "1206 from SM-752 data"
  rect 1.3x1.85 smd: 1(-1.45,0) 2(1.45,0)
  silkscreen extent -2.4,-1.21 2.4,1.21, body extent -1.7,-0.9 1.7,0.9, height 1.35
1206_180 [mm] "1206_180"
  rect 1.1x1.6 smd: 1(-1.7,0) 2(1.7,0)
  silkscreen extent -0.9,-1 0.9,1, body extent -1.75,-0.95 1.75,0.95, height 1.8
1210_280 [mm] "SMD, 2-Leads, Body 3.6x2.8mm, Height 2.8mm"
  rect 1.1x2.2 smd: 1(-1.65,0) 2(1.65,0)
  silkscreen extent -0.84,-1.4 0.84,1.4, body extent -1.8,-1.4 1.8,1.4, height 2.8
2220_280 [mm] "Chip Capacitor, Body 5.7x5.0mm, IPC Medium Density"
  rect 1.6x5.3 smd: 1(-2.6,0) 2(2.6,0)
  silkscreen extent -3.69,-2.94 3.69,2.94, body extent -2.95,-2.62 2.95,2.62, height 2.8
705550039 [mm]
  rrect6% 1.69x1.69 hole 1.09 paste-1000 mask+0: 1(5.09,6.145)
  round 1.69 hole 1.09 paste-1000 mask+0: 2(2.55,6.145) 3(0.01,6.145) 4(-2.53,6.145) 5(-5.07,6.145)
  round 3.4 hole 3.4 unplated paste-1000 mask+0: ""(-6.47,-2.495) ""(6.49,-2.495)
  body extent -8.25,-6.91 8.26,6.67, height 7.11
AssemblyNote [mil] "Assembly Note"
CONN_PEC02SAAN [mm] "SULLINS"
  rrect7% 1.5x1.5 hole 1.016: 1(-1.27,0)
  round 1.5 hole 1.016: 2(1.27,0)
  silkscreen extent -2.54,-1.52 2.54,1.27, body extent -2.54,-1.27 2.54,1.27, height 8.38
DBV0005A_N [mm] "SOT23, 5-Leads, Body 2.9x1.6mm, Pitch 0.95mm, Lead Span 2.8mm, IPC Medium Density"
  rrect17% 1x0.6 smd: 1(-1.375,0.95) 2(-1.375,0) 3(-1.375,-0.95) 4(1.375,-0.95) 5(1.375,0.95)
  silkscreen extent -1.63,-1.55 0.38,1.55, body extent -1.42,-1.46 1.42,1.46, height 1.09
DBZ0003A-MFG [mm]
  rrect17% 1.3x0.6 smd paste+0 mask+0: 1(-1.05,0.95) 2(-1.05,-0.95) 3(1.05,0)
  silkscreen extent -0.03,-1.52 0.7,1.52, body extent -1.8,-1.62 1.8,1.62, height 0.25
DGQ0010D-C01-MFG [mm]
  rrect33% 1.45x0.3 smd paste+0 mask+0: 1(-2.2,1) 2(-2.2,0.5) 3(-2.2,0) 4(-2.2,-0.5) 5(-2.2,-1) 6(2.2,-1) 7(2.2,-0.5) 8(2.2,0) 9(2.2,0.5) 10(2.2,1)
  rrect5% 2.2x3.1 smd paste-1000 mask-1000: 11(0,0)
  silkscreen extent -3.6,-1.95 1.55,1.95, body extent -3.03,-1.8 3.03,1.8, height 0.25
DWQ0011A-MFG [mm]
  rrect25% 1.65x0.6 smd paste+0 mask+0: 1(-4.875,4.445) 2(-4.875,3.175) 3(-4.875,1.905) 4(-4.875,0.635) 5(-4.875,-0.635) 6(-4.875,-1.905) 7(-4.875,-3.175) 8(-4.875,-4.445)
  rrect13% 1.65x1.15 smd paste+0 mask+0: 9(4.875,-4.17) 10(4.875,0) 11(4.875,4.17)
  silkscreen extent -6.4,-5.25 3.8,5.25, body extent -5.8,-5.35 5.8,5.35, height 0.25
DWW0016A_N [mm] "SOP, 16-Leads, Body 10.30x14.00mm, Pitch 1.27mm, IPC Medium Density"
  oval 2x0.6 smd: 1(-8.25,4.445) 2(-8.25,3.175) 3(-8.25,1.905) 4(-8.25,0.635) 5(-8.25,-0.635) 6(-8.25,-1.905) 7(-8.25,-3.175) 8(-8.25,-4.445) 9(8.25,-4.445) 10(8.25,-3.175) 11(8.25,-1.905) 12(8.25,-0.635) 13(8.25,0.635) 14(8.25,1.905) 15(8.25,3.175) 16(8.25,4.445)
  silkscreen extent -9.13,-5.2 6.85,5.23, body extent -8.64,-5.17 8.64,5.13, height 2.55
FCC_disclaimer [mil]
Fiducial10-20#1 [mm]
  round 1 smd mask+0.5: 1(0,0)
  Top Layer keep-out circle w1.178: c0,0 r0.5
Fiducial10-20#2 [mm]
  round 1 smd far side mask+0.5: 1(0,0)
  Top Layer keep-out circle w1.178: c0,0 r0.5
FP-2N7002BKS,115_SOT363-MFG [mm]
  rrect17% 0.6x0.6 smd paste-1000 mask+0: 1(-0.9,0.75) 3(-0.9,-0.75) 4(0.9,-0.75) 6(0.9,0.75)
  rrect25% 0.6x0.4 smd paste+0 mask+0: 2(-0.9,0) 5(0.9,0)
  silkscreen extent -1.9,-1.1 0.15,1.1, body extent -1.33,-1.2 1.33,1.2, height 0.25
FP-CHV1206-FX-1504ELF_1206-MFG [mm]
  rrect8% 1.3x1.8 smd paste+0 mask+0: 1(-1.7,0) 2(1.7,0)
  silkscreen extent -0.67,-0.85 0.67,0.85, body extent -2.45,-1 2.45,1, height 0.25
FP-GCM1555C1H221JA16D_0402-MFG [mm]
  rrect25% 0.4x0.5 smd paste+0 mask+0: 1(-0.4,0) 2(0.4,0)
  body extent -0.5,-0.25 0.5,0.25, height 0.55
FP-HCTSM151207FAL_SMT_XFRMR_21MM3_15MM0-MFG [mm]
  rrect8% 2.2x1.25 smd paste+0 mask+0: 1(-8.7,4.5) 2(-8.7,0) 3(-8.7,-4.5) 4(8.7,-4.5) 5(8.7,0) 6(8.7,4.5)
  silkscreen extent -10.47,-7.75 9.5,7.75, body extent -11,-7.85 11,7.85, height 0.25
FP-KT05-1A88-BV88926_SMT_RELAY_10MM2_30MM2-MFG [mm]
  rrect4% 2.4x3.5 smd paste+0 mask+0: 1(-10.15,7.5) 2(10.15,7.5) 3(-13.97,-7.5) 4(13.97,-7.5)
  silkscreen extent -15.1,-5.1 15.1,7.62, body extent -15.1,-8.5 15.1,8.5, height 8.7
FP-LKBMT10B_SMT_XFRMR_27MM9_12MM5-MFG [mm]
  rrect10% 2.55x1.02 smd paste+0 mask+0: 1(-13.225,2.54) 2(-13.225,0) 3(-13.225,-2.54) 4(13.225,-2.54) 5(13.225,0) 6(13.225,2.54)
  silkscreen extent -15.18,-6.38 14.08,6.38, body extent -15.85,-6.48 15.85,6.48, height 0.25
FP-PJ-002BH_PTH_POWER_CONN_14MM4_9MM0-MFG [mm]
  rrect6% 1.6x5.1 hole 4.5 slot 1 at 0 deg paste-1000 mask+0: 1(-6.5,0)
  rrect100% 1.6x4.6 hole 4 slot 1 at 0 deg paste-1000 mask+0: 2(-0.5,0)
  rrect100% 4.6x1.6 hole 4 slot 1 at 90 deg paste-1000 mask+0: 3(-3.5,4.7)
  silkscreen extent -7.3,-4.6 7.3,4.6, body extent -7.4,-4.7 7.4,5.6, height 0.25
FP-PTFR0603B24K9NT_0603-MFG [mm]
  rrect10% 1x1.2 smd paste+0 mask+0: 1(-1,0) 2(1,0)
  silkscreen extent -0.13,-0.5 0.13,0.5, body extent -0.8,-0.4 0.8,0.4, height 0.5
FP-SMCJ36A_DO-214AB-MFG [mm]
  rrect4% 2.4x3.3 smd paste+0 mask+0: 1(-3.3,0) 2(3.3,0)
  silkscreen extent -5.2,-3.11 3.55,3.11, body extent -4.6,-3.21 4.6,3.21, height 0.25
FP-TSW-105-08-L-D-RA_HDR10-MFG [mm]
  rrect6% 1.57x1.57 hole 1.02 paste-1000 mask+0: 1(-5.08,2.79)
  round 1.57 hole 1.02 paste-1000 mask+0: 2(-5.08,5.33) 3(-2.54,2.79) 4(-2.54,5.33) 5(0,2.79) 6(0,5.33) 7(2.54,2.79) 8(2.54,5.33) 9(5.08,2.79) 10(5.08,5.33)
  body extent -6.64,-7.47 6.64,6.21, height 0.25
IEC_HighVoltage_Small [mil]
  silkscreen extent -107,-88 107,97
IHLP-1616BZ [mm] "Vishay Dale recommended land pattern."
  rect 1.65x2.3 smd: 1(-1.65,0) 2(1.65,0)
  silkscreen extent -2.45,-2.25 2.45,2.25, body extent -2.35,-2.16 2.35,2.16, height 2
Keystone1598-2 [mm] "Triple Turret"
  round 3.5 hole 2.5: 1(0,0)
  silkscreen extent -2.08,-2.08 2.08,2.08, body extent -1.6,-1.6 1.59,1.6, height 7.72
Keystone5012 [mil] "Keystone Multipurpose loops"
  round 87 hole 63: 1(0,0)
  silkscreen extent -70,-70 70,70, body extent -63,-63 63,62, height 319
Keystone_1902C [mil] "Hex Standoff, 4-40 threaded, nylon"
  round 1 on Mech3: 0(0,0)
  body extent -145,-126 146,126, height 501
Label_650x200 [mil] "Thermal Transfer Label"
  round 1 on Mech13: 0(0,0)
  silkscreen extent -325,-100 325,100, body extent -325,-100 325,100, height 1
Molex_70551-0038 [mm] "Header(shrouded), 2.54mm, 4x1, R/A, TH"
  rect 1.6x1.6 hole 1.09: 1(0,3.81)
  round 1.6 hole 1.09: 2(0,1.27) 3(0,-1.27) 4(0,-3.81)
  round 0 hole 3.4 unplated paste+0 mask+0: MH1(8.64,-5.08) MH2(8.64,5.08)
  silkscreen extent 1.45,-6.98 12.88,7.32, body extent -0.71,-6.98 12.88,6.98, height 6.6
"NY PMS 440 0025 PH" [mm] "4-40 nylon screw and mounting hole"
  round 8 hole 3.2: 1(0,0)
  body extent -3.3,-3.3 3.3,3.3, height 2.69
Pb-Free_Overlay_Small [mil]
  silkscreen extent -46,-46 46,46
Phoenix_1792119 [mm] "Receptacle, 7.5mm, 3x1, TH"
  rect 2.5x2.5 hole 2: 1(-7.5,-6.25)
  round 2.5 hole 2: 2(0,6.25) 3(7.5,-6.25)
  silkscreen extent -12.3,-14.5 11.95,8.25, body extent -11.75,-14.5 11.95,8.25, height 24.1
PHP0048E-MFG [mm]
  rrect33% 1.6x0.3 smd paste-1000 mask+0: 1(-4.1,2.75) 2(-4.1,2.25) 3(-4.1,1.75) 4(-4.1,1.25) 5(-4.1,0.75) 6(-4.1,0.25) 7(-4.1,-0.25) 8(-4.1,-0.75) 9(-4.1,-1.25) 10(-4.1,-1.75) 11(-4.1,-2.25) 12(-4.1,-2.75) 25(4.1,-2.75) 26(4.1,-2.25) 27(4.1,-1.75) 28(4.1,-1.25) 29(4.1,-0.75) 30(4.1,-0.25) 31(4.1,0.25) 32(4.1,0.75) 33(4.1,1.25) 34(4.1,1.75) 35(4.1,2.25) 36(4.1,2.75)
  rrect33% 0.3x1.6 smd paste-1000 mask+0: 13(-2.75,-4.1) 14(-2.25,-4.1) 15(-1.75,-4.1) 16(-1.25,-4.1) 17(-0.75,-4.1) 18(-0.25,-4.1) 19(0.25,-4.1) 20(0.75,-4.1) 21(1.25,-4.1) 22(1.75,-4.1) 23(2.25,-4.1) 24(2.75,-4.1) 37(2.75,4.1) 38(2.25,4.1) 39(1.75,4.1) 40(1.25,4.1) 41(0.75,4.1) 42(0.25,4.1) 43(-0.25,4.1) 44(-0.75,4.1) 45(-1.25,4.1) 46(-1.75,4.1) 47(-2.25,4.1) 48(-2.75,4.1)
  rrect3% 3.62x3.62 smd paste+0 mask+0: 49(0,0)
  silkscreen extent -5.6,-3.6 3.6,3.6, body extent -5,-5 5,5, height 0.25
Samtec_HTSW-102-09-x-S [mm] "Header, 2x1, 2.54mm, TH"
  rect 1.55x1.55 hole 1.02: 1(-1.27,0)
  round 1.55 hole 1.02: 2(1.27,0)
  silkscreen extent -2.54,-1.24 2.54,1.6, body extent -2.54,-1.24 2.54,1.24, height 8.38
Samtec_TSW-102-08-x-S [mm] "Header, 2.54mm, 2x1, TH"
  rrect50% 1.53x1.53 hole 1.02: 1(-1.27,0)
  round 1.53 hole 1.02: 2(1.27,0)
  silkscreen extent -2.67,-1.27 2.54,1.7, body extent -2.67,-1.27 2.54,1.27, height 8.38
Samtec_TSW-104-08-x-D [mm] "Header, 2.54mm, 4x2, TH"
  rrect50% 1.55x1.55 hole 1.02: 1(-1.27,3.81)
  round 1.55 hole 1.02: 2(1.27,3.81) 3(-1.27,1.27) 4(1.27,1.27) 5(-1.27,-1.27) 6(1.27,-1.27) 7(-1.27,-3.81) 8(1.27,-3.81)
  silkscreen extent -3,-5.08 2.54,5.08, body extent -2.54,-5.08 2.54,5.08, height 8.38
SM_RADIAL_G [mm] "10 x 10.2mm:  Panasonic G"
  rect 4.1x2 smd: 1(-4.35,0) 2(4.35,0)
  silkscreen extent -5.35,-5.35 5.35,5.35, body extent -5.25,-5.25 5.25,5.25, height 10.5
SMA [mm] "Molded Diode, 2-Leads, Body 4.3x2.6mm, IPC Medium Density, based on OnSemi component dimensions and land pattern"
  rect 2x2 smd: 1(-2,0) 2(2,0)
  silkscreen extent -3.66,-1.57 2.79,1.57, body extent -2.6,-1.3 2.6,1.3, height 2.42
SOD-123 [mm] "On Semi recommended land pattern"
  rect 0.915x1.22 smd: 1(-1.637,0) 2(1.637,0)
  silkscreen extent -2.74,-1.17 2.03,1.17, body extent -1.93,-0.9 1.93,0.9, height 1.35
SOD-323-Bi [mm] "SOD323, 2-Leads, Body 1.9x1.45mm, No Polarity Mark"
  rect 0.6x0.6 smd paste-0.05: 1(-1.1,0) 2(1.1,0)
  silkscreen extent -1.53,-0.77 1.53,0.77, body extent -1.27,-0.65 1.27,0.65, height 1.02
SOT-23L [mm] "SOT23, 3-Leads, Body 2.9x1.3mm, Pitch 0.95mm, Lead Span 2.5mm, IPC High Density"
  rrect50% 0.8x0.6 smd: 1(-1.1,0.95) 2(-1.1,-0.95) 3(1.1,0)
  silkscreen extent -1.5,-1.5 0.7,1.5, body extent -1.16,-1.45 1.21,1.45, height 1
TNPV1206 [mm] "VISHAY"
  rrect11% 0.9x1.7 smd: 1(-1.6,0) 2(1.6,0)
  silkscreen extent -2.4,-1.2 2.4,1.2, body extent -1.67,-0.87 1.67,0.87, height 0.65
TSW-101-07-G-S [mm] "Samtec 100mil, 1pos, 230 mil above insulator"
  rrect6% 1.65x1.65 hole 1.016: 1(0,0)
  silkscreen extent -1.27,-1.27 1.27,1.27, body extent -1.27,-1.27 1.27,1.27, height 8.38
TSW-103-07-G-D [mm] "Samtec 100mil, 2x3, 230 mil above insulator"
  rect 1.65x1.65 hole 1.016: 1(-2.54,-1.27)
  round 1.65 hole 1.016: 2(-2.54,1.27) 3(0,-1.27) 4(0,1.27) 5(2.54,-1.27) 6(2.54,1.27)
  silkscreen extent -4.84,-2.54 3.81,2.54, body extent -3.81,-2.54 3.81,2.54, height 8.38
TSW-103-07-G-S [mm] "Samtec 100mil, 1x3, 230 mil above insulator"
  rrect50% 1.65x1.65 hole 1.016: 1(-2.54,0)
  round 1.65 hole 1.016: 2(0,0) 3(2.54,0)
  body extent -3.81,-1.27 3.81,1.27, height 8.38
TSW-105-07-G-D [mm] "Samtec 100mil, 2x5, 230 mil above insulator"
  rrect6% 1.65x1.65 hole 1.016: 1(-5.08,-1.27)
  round 1.65 hole 1.016: 2(-5.08,1.27) 3(-2.54,-1.27) 4(-2.54,1.27) 5(0,-1.27) 6(0,1.27) 7(2.54,-1.27) 8(2.54,1.27) 9(5.08,-1.27) 10(5.08,1.27)
  silkscreen extent -7.37,-2.54 6.35,2.54, body extent -6.35,-2.54 6.35,2.54, height 8.38
TSW-108-07-G-D [mm] "Samtec 100mil, 2x8, 230 mil above insulator"
  rrect6% 1.65x1.65 hole 1.016: 1(-8.89,-1.27)
  round 1.65 hole 1.016: 2(-8.89,1.27) 3(-6.35,-1.27) 4(-6.35,1.27) 5(-3.81,-1.27) 6(-3.81,1.27) 7(-1.27,-1.27) 8(-1.27,1.27) 9(1.27,-1.27) 10(1.27,1.27) 11(3.81,-1.27) 12(3.81,1.27) 13(6.35,-1.27) 14(6.35,1.27) 15(8.89,-1.27) 16(8.89,1.27)
  silkscreen extent -11.19,-2.54 10.16,2.54, body extent -10.16,-2.54 10.16,2.54, height 8.38
WEEE_Minimum [mil] "WEEElie bin"
  silkscreen extent -95,-172 99,104
WL-SMCW_GREEN [mm] "WURTH"
  rect 0.8x0.8 smd: 1(-0.8,0) 2(0.8,0)
  silkscreen extent -1.9,-0.8 1.2,0.8, body extent -0.85,-0.45 0.85,0.45, height 0.8
WL-SMCW_RED [mm] "WURTH"
  rect 0.8x0.8 smd: 1(-0.8,0) 2(0.8,0)
  silkscreen extent -1.9,-0.8 1.2,0.8, body extent -0.85,-0.45 0.85,0.45, height 0.8

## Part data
C1: library part CMP-0007088-4, "CAP, CERM, 4700 pF, 100 V, +/- 10%, X7R, AEC-Q200 Grade 1, 0603", Cap_Case=0603, Manufacturer=TDK, Supplier Part Number 1=445-5810-1-ND, TempCo=X7R, Tolerance_%=10%, Value1="0.469862 ohm", Value2=100V, ValueDisplayed=4700pF
C2 C3: library part CMP-0009420-2, "CAP, CERM, 15 uF, 100 V, +/- 20%, X7S, AEC-Q200 Grade 1, 2220", Cap_Case=2220_280, Manufacturer=TDK, Supplier Part Number 1=445-7948-1-ND, TempCo=X7S, Tolerance_%=20%, Value1="0.002642 ohm", Value2=100V, ValueDisplayed=15uF
C4 C7 C21 C24: library part CMP-0009164-2, "CAP, CERM, 10 uF, 50 V, +/- 10%, X7S, AEC-Q200 Grade 1, 1210", Cap_Case=1210_280, Manufacturer=TDK, Supplier Part Number 1=445-7004-1-ND, TempCo=X7S, Tolerance_%=10%, Value1="0.002827 ohm", Value2=50V, ValueDisplayed=10uF
C5: library part CMP-0084240-1, "CAP, CERM, 0.1 µF, 50 V,+/- 20%, X8R, AEC-Q200 Grade 0, 0603", Cap_Case=0603, Manufacturer=TDK, TempCo=X8R, Tolerance_%=20%, Value2=50V, ValueDisplayed=0.1µF
C6 C9: library part CMP-0006309-2, "CAP, CERM, 1000 pF, 50 V, +/- 5%, C0G/NP0, AEC-Q200 Grade 1, 0402", Cap_Case=0402, Manufacturer=TDK, Supplier Part Number 1=445-6885-1-ND, TempCo=C0G/NP0, Tolerance_%=5%, Value1=Unknown, Value2=50V, ValueDisplayed=1000pF
C8: library part CMP-0007977-2, "CAP, CERM, 2.2 uF, 50 V, +/- 10%, X7R, AEC-Q200 Grade 1, 0805", Cap_Case=0805, Manufacturer=TDK, Supplier Part Number 1=445-174216-1-ND, TempCo=X7R, Tolerance_%=10%, Value1="0.003288 ohm", Value2=50V, ValueDisplayed=2.2uF
C10: library part CMP-0011180-2, "CAP, AL, 220 uF, 50 V, +/- 20%, 0.18 ohm, AEC-Q200 Grade 2, SMD", Cap_Case=G, Manufacturer=Panasonic, Supplier Part Number 1=PCE4324CT-ND, Tolerance_%=20%, Value1="0.18 ohm", Value2=50V, ValueDisplayed=220uF
C11: library part CMP-0006412-2, "CAP, CERM, 1000 pF, 50 V, +/- 5%, C0G/NP0, 0402", Cap_Case=0402, Manufacturer=MuRata, Supplier Part Number 1=490-3244-1-ND, TempCo=C0G/NP0, Tolerance_%=5%, Value1=Unknown, Value2=50V, ValueDisplayed=1000pF
C12 C92 C301: library part CMP-0081052-1, "CAP, CERM, 4.7 µF, 16 V,+/- 10%, X5R, AEC-Q200 Grade 3, 0603", Cap_Case=0603, Manufacturer=MuRata, Supplier Part Number 1=490-12319-1-ND, TempCo=X5R, Tolerance_%=10%, Value2=16V, ValueDisplayed=4.7µF
C13 C300: library part CMP-0009015-2, "CAP, CERM, 10 uF, 50 V, +/- 10%, X5R, AEC-Q200 Grade 1, 1206", Cap_Case=1206, Manufacturer=MuRata, Supplier Part Number 1=490-12456-1-ND, TempCo=X5R, Tolerance_%=10%, Value1=Unknown, Value2=50V, ValueDisplayed=10uF
C14 C49 C70 C71 C74 C75 C76 C77 C80 C81 C82 C84: library part CMP-0084679-1, "CAP, CERM, 0.1 µF, 25 V,+/- 10%, X7R, AEC-Q200 Grade 1, 0603", Cap_Case=0603, Manufacturer=MuRata, TempCo=X7R, Tolerance_%=10%, Value2=25V, ValueDisplayed=0.1µF
C22 C23 C25 C27 C28 C29 C30 C31 C89 C91 C93 C150: library part CMP-0006356-2, "CAP, CERM, 0.1 uF, 50 V, +/- 10%, X7R, AEC-Q200 Grade 1, 0402", Cap_Case=0402, Manufacturer=MuRata, Supplier Part Number 1=490-10672-1-ND, TempCo=X7R, Tolerance_%=10%, Value1=Unknown, Value2=50V, ValueDisplayed=0.1uF
C26: library part CMP-0084284-1, "CAP, CERM, 2.2 µF, 10 V,+/- 10%, X7R, AEC-Q200 Grade 1, 0603", Cap_Case=0603, Manufacturer=MuRata, TempCo=X7R, Tolerance_%=10%, Value2=10V, ValueDisplayed=2.2µF
C72 C78: library part CMP-0007139-4, "CAP, CERM, 1 uF, 25 V, +/- 10%, X7R, AEC-Q200 Grade 1, 0603", Cap_Case=0603, Manufacturer=MuRata, Supplier Part Number 1=490-10673-1-ND, TempCo=X7R, Tolerance_%=10%, Value1=Unknown, Value2=25V, ValueDisplayed=1uF
C73 C79: library part CMP-0088015-1, "220pF Multilayer Ceramic Capacitor (MLCC) 50 V dc 5% C0G dielectric GCM max op. temp. +125C", Manufacturer="Murata Electronics North America", TempCo=30ppm/°C, Tolerance_%=5%, ValueDisplayed=220pF
C83 C85: library part CMP-0007086-4, "CAP, CERM, 0.022 uF, 100 V, +/- 10%, X7R, AEC-Q200 Grade 1, 0603", Cap_Case=0603, Manufacturer=TDK, Supplier Part Number 1=445-5814-1-ND, TempCo=X7R, Tolerance_%=10%, Value1="0.083542 ohm", Value2=100V, ValueDisplayed=0.022uF
C87 C88 C94 C95: library part CMP-0006580-2, "CAP, CERM, 0.47 uF, 10 V, +/- 10%, X5R, 0402", Cap_Case=0402, Manufacturer=MuRata, Supplier Part Number 1=490-3264-1-ND, TempCo=X5R, Tolerance_%=10%, Value1=Unknown, Value2=10V, ValueDisplayed=0.47uF
C90: library part CMP-0006361-2, "CAP, CERM, 4700 pF, 50 V, +/- 10%, X7R, AEC-Q200 Grade 1, 0402", Cap_Case=0402, Manufacturer=MuRata, Supplier Part Number 1=490-4915-1-ND, TempCo=X7R, Tolerance_%=10%, Value1=Unknown, Value2=50V, ValueDisplayed=4700pF
C98 C101 C104 C107: library part CMP-0860329-1, "CAP, CERM, 220 pF, 50 V,+/- 5%, X7R, 0603", Cap_Case=0603, Manufacturer="Samsung Electro-Mechanics", TempCo=X7R, Tolerance_%=5%, Value2=50V, ValueDisplayed=220pF
C99 C105: library part CMP-0750041-1, "CAP, CERM, 100 pF, 50 V,+/- 5%, C0G/NP0, AEC-Q200 Grade 1, 0603", Cap_Case=0603, Manufacturer=MuRata, TempCo=C0G/NP0, Tolerance_%=5%, Value2=50V, ValueDisplayed=100pF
